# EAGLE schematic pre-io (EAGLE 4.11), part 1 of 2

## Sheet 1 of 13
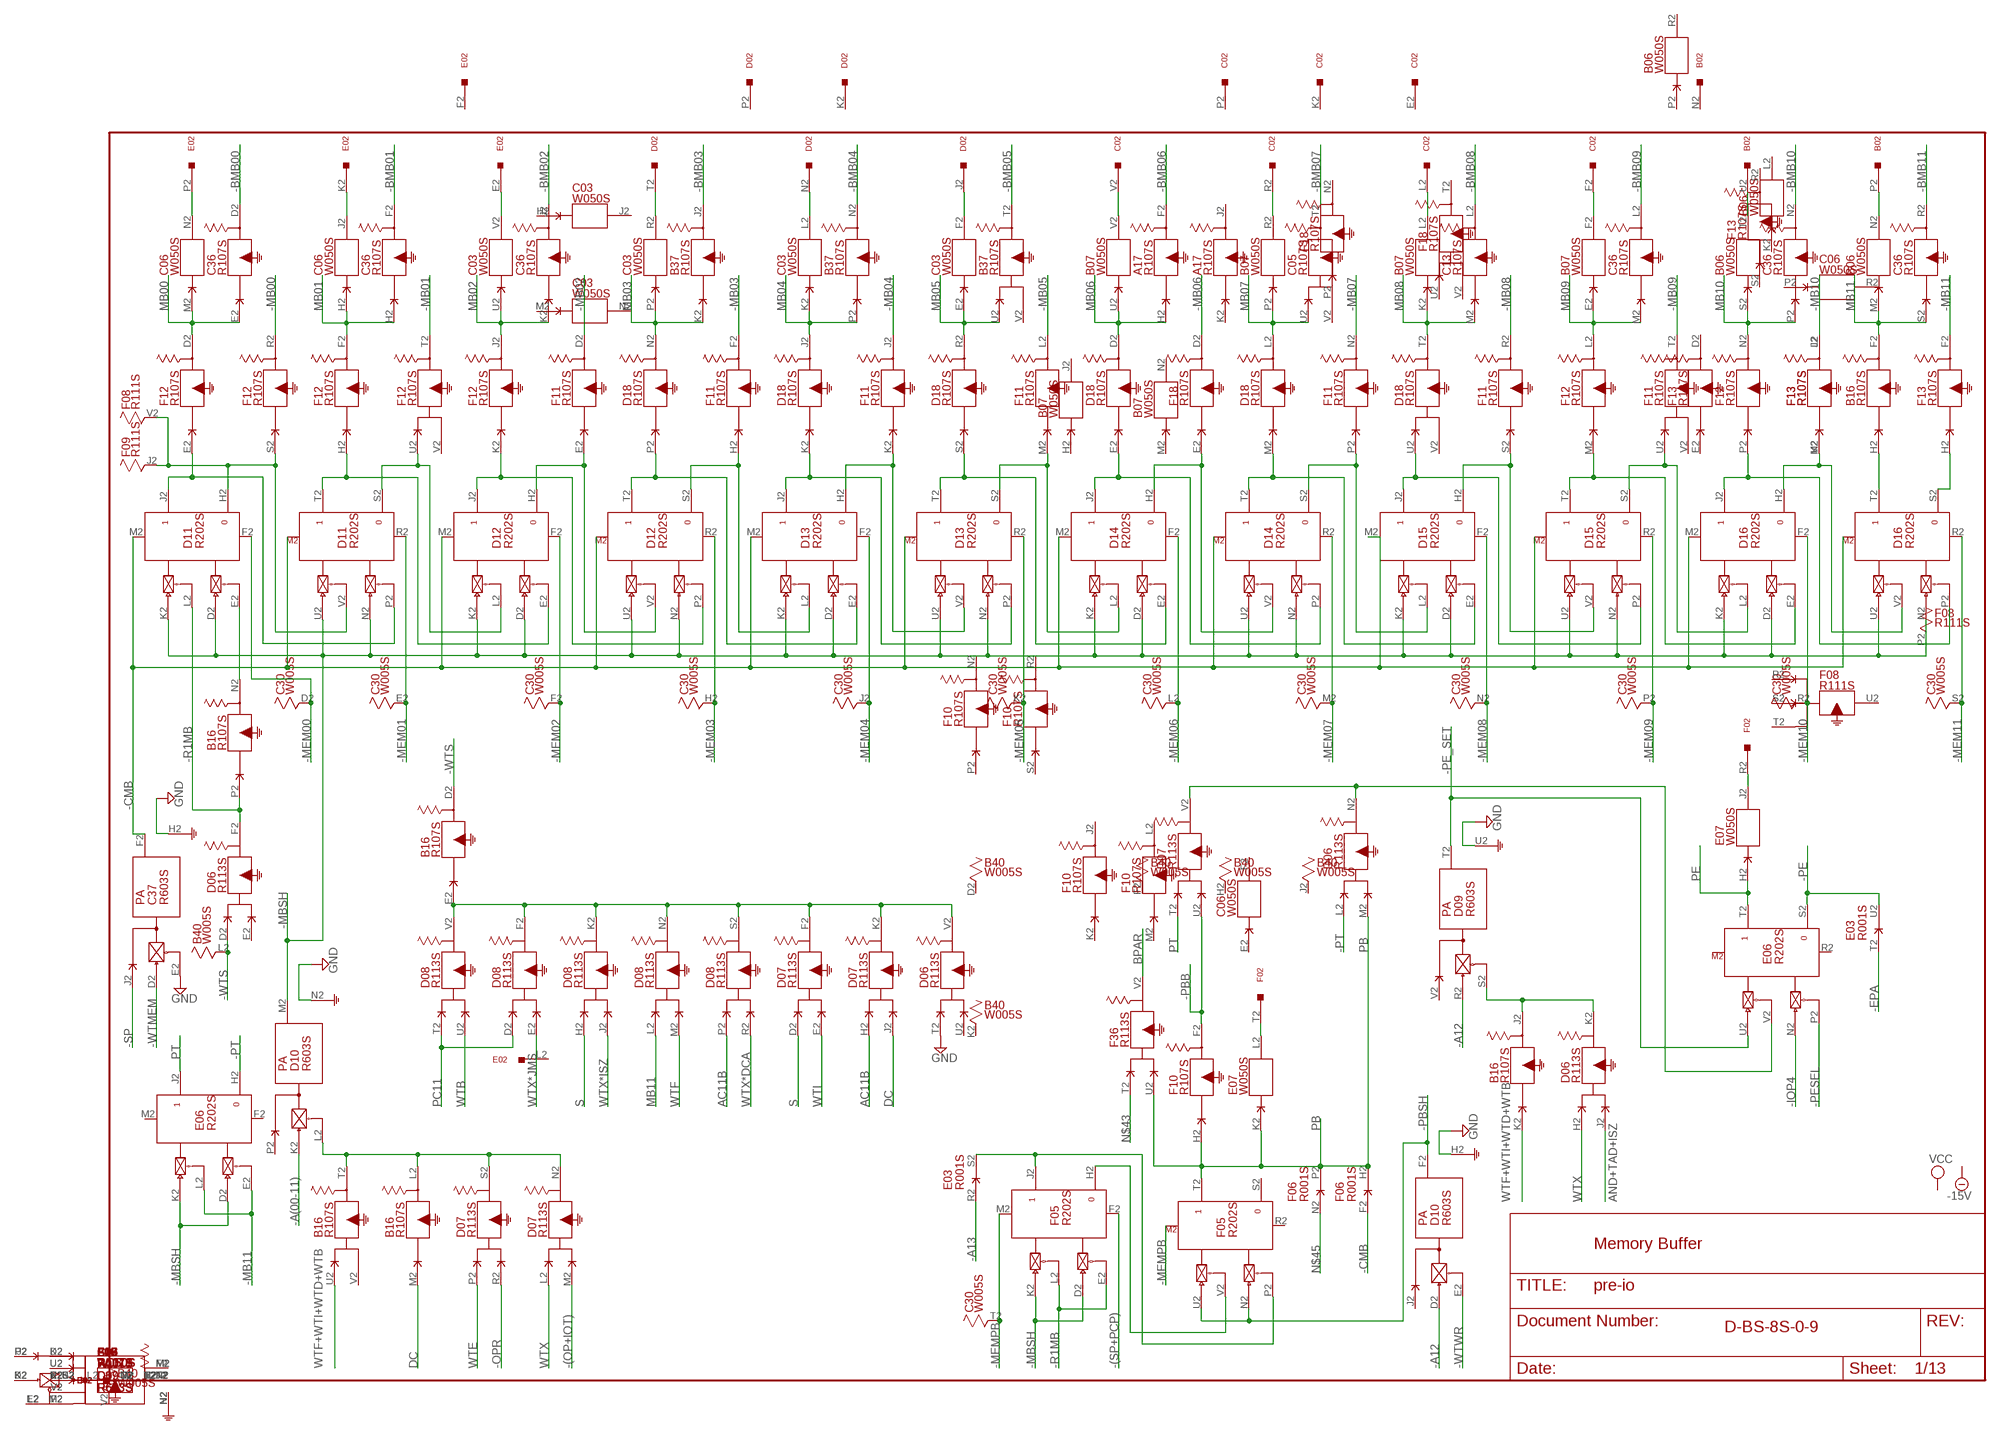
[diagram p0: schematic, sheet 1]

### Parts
A17  R107S  [H807S]
B02  W023S  [H807S]
B06  W050S  [H807S]
B07  W050S  [H807S]
B16  R107S  [H807S]
B37  R107S  [H807S]
B40  W005S  [H807S]
C02  W023S  [H807S]
C03  W050S  [H807S]
C05  R107S  [H807S]
C06  W050S  [H807S]
C13  R107S  [H807S]
C30  W005S  [H807S]
C36  R107S  [H807S]
C37  R603S  [H807S]
D02  W023S  [H807S]
D06  R113S  [H807S]
D07  R113S  [H807S]
D08  R113S  [H807S]
D09  R603S  [H807S]
D10  R603S  [H807S]
D11  R202S  [H807S]
D12  R202S  [H807S]
D13  R202S  [H807S]
D14  R202S  [H807S]
D15  R202S  [H807S]
D16  R202S  [H807S]
D18  R107S  [H807S]
E02  W023S  [H807S]
E03  R001S  [H807S]
E06  R202S  [H807S]
E07  W050S  [H807S]
F02  W023S  [H807S]
F05  R202S  [H807S]
F06  R001S  [H807S]
F08  R111S  [H807S]
F09  R111S  [H807S]
F10  R107S  [H807S]
F11  R107S  [H807S]
F12  R107S  [H807S]
F13  R107S  [H807S]
F18  R107S  [H807S]
F36  R113S  [H807S]

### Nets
-(OP+IOT): D07.M2(N:I$2) ; also sheet 6,9
-(SP+PCP): F05.F2(J:RESET) ; also sheet 3,7,8
-A12: D09.R2(T:PU0) D10.D2(F:PU0) ; also sheet 3,4,6,8
-A13: E03.R2(S:D) ; also sheet 4,5,6,7
-A(00-11): D10.K2(M:PU0) ; also sheet 3,4,5,7,9
-BMB00: C36.D2(D:O$1)
-BMB01: C36.F2(F:O$1)
-BMB02: C36.J2(J:O$1)
-BMB03: B37.J2(J:O$1)
-BMB04: B37.N2(N:O$1)
-BMB05: B37.T2(T:O$1)
-BMB06: A17.F2(F:O$1)
-BMB07: C05.T2(T:O$1)
-BMB08: C13.L2(L:O$1)
-BMB09: C36.L2(L:O$1)
-BMB10: C36.N2(N:O$1)
-BMB11: C36.R2(R:O$1)
-CMB: C37.F2(F:O) D11.M2(J:SET) D12.M2(J:SET) D13.M2(J:SET) D14.M2(J:SET) D15.M2(J:SET) D16.M2(J:SET) F06.F2(H:D)
-EPA: E03.T2(U:D) ; also sheet 8
-IOP4: E06.N2(T:PU0)
-MB00: F12.R2(R:O$1) ; also sheet 2
-MB01: F12.T2(T:O$1) ; also sheet 2
-MB02: F11.D2(D:O$1) ; also sheet 2
-MB03: F11.F2(F:O$1) ; also sheet 2
-MB04: F11.J2(J:O$1) ; also sheet 2,5
-MB05: F11.L2(L:O$1) ; also sheet 2,6
-MB06: F18.D2(D:O$1) ; also sheet 2,6,7
-MB07: F11.N2(N:O$1) ; also sheet 2,6
-MB08: F11.R2(R:O$1) ; also sheet 2,3
-MB09: F11.T2(T:O$1) ; also sheet 2
-MB10: F13.L2(L:O$1) ; also sheet 2,9
-MB11: E06.E2(J:EN0) E06.L2(J:EN1) F13.F2(F:O$1) ; also sheet 2,9
-MBSH: D10.M2(M:O) D11.D2(J:PU0) D11.K2(J:PU1) D11.N2(T:PU0) D11.U2(T:PU1) D12.D2(J:PU0) D12.K2(J:PU1) D12.N2(T:PU0) D12.U2(T:PU1) D13.D2(J:PU0) D13.K2(J:PU1) D13.N2(T:PU0) D13.U2(T:PU1) D14.D2(J:PU0) D14.K2(J:PU1) D14.N2(T:PU0) D14.U2(T:PU1) D15.D2(J:PU0) D15.K2(J:PU1) D15.N2(T:PU0) D15.U2(T:PU1) D16.D2(J:PU0) D16.K2(J:PU1) D16.N2(T:PU0) D16.U2(T:PU1) E06.D2(J:PU0) E06.K2(J:PU1) F05.D2(J:PU0) F05.K2(J:PU1)
-MEM00: C30.D2 D11.F2(J:RESET) ; also sheet 2
-MEM01: C30.E2 D11.R2(T:RESET) ; also sheet 2
-MEM02: C30.F2 D12.F2(J:RESET) ; also sheet 2
-MEM03: C30.H2 D12.R2(T:RESET) ; also sheet 2
-MEM04: C30.J2 D13.F2(J:RESET) ; also sheet 2
-MEM05: C30.K2 D13.R2(T:RESET) ; also sheet 2
-MEM06: C30.L2 D14.F2(J:RESET) ; also sheet 2
-MEM07: C30.M2 D14.R2(T:RESET) ; also sheet 2
-MEM08: C30.N2 D15.F2(J:RESET) ; also sheet 2
-MEM09: C30.P2 D15.R2(T:RESET) ; also sheet 2
-MEM10: C30.R2 D16.F2(J:RESET) ; also sheet 2
-MEM11: C30.S2 D16.R2(T:RESET) ; also sheet 2
-MEMPB: C30.T2 F05.M2(J:SET) ; also sheet 2
-OPR: D07.R2(S:I$2) ; also sheet 9
-PBB: D07.U2(V:I$2) F10.F2(F:O$1) ; also sheet 2
-PBSH: D10.F2(F:O) F05.N2(T:PU0) F05.U2(T:PU1)
-PE: E03.U2(U:E) E06.S2
-PE_SET: D09.T2(T:O) E06.U2(T:PU1)
-PESEL: E06.P2(T:EN0)
-PT: D06.L2(N:I$1) E06.H2
-R1MB: B16.P2(N:I$1) D06.F2(F:O$1) D11.L2(J:EN1) F05.E2(J:EN0) F05.L2(J:EN1)
-SP: C37.J2(F:I$1) ; also sheet 6,8
-WTMEM: C37.D2(F:PU0)
-WTS: B16.D2(D:O$1) B40.L2 D06.D2(F:I$1) ; also sheet 4,6
-WTWR: D10.E2(F:EN0) ; also sheet 6
AC11B: D07.H2(K:I$1) D08.P2(S:I$1) ; also sheet 7
AND+TAD+ISZ: D06.J2(K:I$2) ; also sheet 9
BPAR: F36.V2(V:O$1)
DC: B16.M2(L:I$1) D07.J2(K:I$2) ; also sheet 8
GND [Supply]: C37.E2(F:EN0) C37.H2(F:G) D06.T2(V:I$1) D09.U2(T:G) D10.H2(F:G) D10.N2(M:G) ; also sheet 2,3,4,5,6,7,8,9
MB00: C06.M2(N:I$1) C36.E2(D:I$1) F12.D2(D:O$1)
MB01: C06.H2(J:I$1) C36.H2(F:I$1) F12.F2(F:O$1)
MB02: C03.U2(V:I$1) C36.K2(J:I$1) F12.J2(J:O$1)
MB03: B37.K2(J:I$1) C03.P2(R:I$1) D18.N2(N:O$1)
MB04: B37.P2(N:I$1) C03.K2(L:I$1) D18.J2(J:O$1)
MB05: B37.U2(T:I$1) C03.E2(F:I$1) D18.R2(R:O$1) ; also sheet 3,9
MB06: A17.H2(F:I$1) B07.U2(V:I$1) D18.D2(D:O$1) ; also sheet 3,7,9
MB07: B07.P2(R:I$1) C05.U2(T:I$1) D18.L2(L:O$1) ; also sheet 3,9
MB08: B07.K2(L:I$1) C13.M2(L:I$1) D18.T2(T:O$1) ; also sheet 3,6,9
MB09: B07.E2(F:I$1) C36.M2(L:I$1) F12.L2(L:O$1) ; also sheet 3,9
MB10: B06.S2(T:I$1) C36.P2(N:I$1) F12.N2(N:O$1) ; also sheet 8,9
MB11: B06.M2(N:I$1) B16.F2(F:O$1) C36.S2(R:I$1) D08.L2(N:I$1) ; also sheet 6,7,9
N$1: D11.J2 D11.P2(T:EN0) F12.E2(D:I$1)
N$2: C06.N2(N:O$1) E02.P2
N$3: D11.H2 D11.V2(T:EN1) F08.V2 F09.J2 F12.S2(R:I$1)
N$4: D11.T2 D12.E2(J:EN0) F12.H2(F:I$1)
N$5: B16.E2(D:I$1) D06.V2(V:O$1) D07.F2(F:O$1) D07.K2(K:O$1) D08.F2(F:O$1) D08.K2(K:O$1) D08.N2(N:O$1) D08.S2(S:O$1) D08.V2(V:O$1)
N$6: D12.J2 D12.P2(T:EN0) F12.K2(J:I$1)
N$7: D12.T2 D13.E2(J:EN0) D18.P2(N:I$1)
N$8: D13.J2 D13.P2(T:EN0) D18.K2(J:I$1)
N$9: D13.T2 D14.E2(J:EN0) D18.S2(R:I$1)
N$10: D14.J2 D14.P2(T:EN0) D18.E2(D:I$1)
N$11: D14.T2 D15.E2(J:EN0) D18.M2(L:I$1)
N$12: D15.J2 D15.P2(T:EN0) D18.U2(T:I$1)
N$13: D15.H2 D15.V2(T:EN1) F11.S2(R:I$1)
N$14: D14.S2 D15.L2(J:EN1) F11.P2(N:I$1)
N$15: D14.H2 D14.V2(T:EN1) F18.E2(D:I$1)
N$16: D13.S2 D14.L2(J:EN1) F11.M2(L:I$1)
N$17: D15.T2 D16.E2(J:EN0) F12.M2(L:I$1)
N$18: D15.S2 D16.L2(J:EN1) F11.U2(T:I$1)
N$19: D16.J2 D16.P2(T:EN0) F12.P2(N:I$1)
N$20: D13.H2 D13.V2(T:EN1) F11.K2(J:I$1)
N$21: D12.S2 D13.L2(J:EN1) F11.H2(F:I$1)
N$22: D12.H2 D12.V2(T:EN1) F11.E2(D:I$1)
N$23: D11.S2 D12.L2(J:EN1) F12.U2(T:I$1)
N$24: D16.H2 D16.V2(T:EN1) F13.M2(L:I$1)
N$25: B16.H2(F:I$1) D16.T2
N$26: D16.S2 F13.H2(F:I$1)
N$27: C06.J2(J:O$1) E02.K2
N$28: C03.V2(V:O$1) E02.E2
N$29: C03.R2(R:O$1) D02.T2
N$30: C03.L2(L:O$1) D02.N2
N$31: C03.F2(F:O$1) D02.J2
N$32: B07.V2(V:O$1) C02.V2
N$33: B07.R2(R:O$1) C02.R2
N$34: B07.L2(L:O$1) C02.L2
N$35: B07.F2(F:O$1) C02.F2
N$36: B02.U2 B06.T2(T:O$1)
N$37: B02.P2 B06.N2(N:O$1)
N$38: B16.L2(L:O$1) B16.T2(T:O$1) D07.N2(N:O$1) D07.S2(S:O$1) D10.L2(M:EN0)
N$39: B16.N2(N:O$1) D11.E2(J:EN0)
N$40: B16.J2(J:O$1) D06.K2(K:O$1) D09.S2(T:EN0)
N$41: E07.J2(J:O$1) F02.R2
N$42: D06.N2(N:O$1) D07.V2(V:O$1) E06.V2(T:EN1)
N$43: F36.T2(V:I$1)
N$44: E07.L2(L:O$1) F02.T2
N$45: F06.N2(P:D)
N$46: F05.H2 F05.V2(T:EN1)
N$47: E03.S2(S:E) F05.J2 F05.P2(T:EN0)
PB: D06.M2(N:I$2) E07.K2(L:I$1) F05.T2 F06.H2(H:E) F06.P2(P:E) F10.H2(F:I$1) F36.U2(V:I$2)
PC11: D08.D2(F:I$1) D08.T2(V:I$1) ; also sheet 5,7
PE: E06.T2 E07.H2(J:I$1)
PT: D07.T2(V:I$1) E06.J2
S: D07.D2(F:I$1) D08.H2(K:I$1) ; also sheet 5,7
WTB: D08.U2(V:I$2) ; also sheet 6
WTE: D07.P2(S:I$1) ; also sheet 3,6,8
WTF: D08.M2(N:I$2) ; also sheet 3,5,6,8
WTF+WTI+WTD+WTB: B16.K2(J:I$1) B16.U2(T:I$1) ; also sheet 6
WTI: D07.E2(F:I$2) ; also sheet 6
WTX: D06.H2(K:I$1) D07.L2(N:I$1) ; also sheet 3,6,7
WTX*DCA: D08.R2(S:I$2) ; also sheet 6
WTX*ISZ: D08.J2(K:I$2) ; also sheet 6
WTX*JMS: D08.E2(F:I$2) ; also sheet 6
Unconnected: A17.D2(D:O$1) A17.E2(D:I$1) A17.L2(L:O$1) A17.M2(L:I$1) A17.R2(R:O$1) A17.S2(R:I$1) A17.T2(T:O$1) A17.U2(T:I$1) A17.V2(T:I$2) B02.A2 B02.B2 B02.C2 B02.E2 B02.F2 B02.H2 B02.J2 B02.K2 B02.L2 B02.M2 B02.R2 B02.S2 B02.V2 B06.E2(F:I$1) B06.F2(F:O$1) B06.H2(J:I$1) B06.J2(J:O$1) B16.R2(R:O$1) B16.S2(R:I$1) B16.V2(T:I$2) B37.D2(D:O$1) B37.E2(D:I$1) B37.F2(F:O$1) B37.H2(F:I$1) B37.L2(L:O$1) B37.M2(L:I$1) B37.R2(R:O$1) B37.S2(R:I$1) B37.V2(T:I$2) B40.E2 B40.M2 B40.N2 B40.P2 B40.R2 B40.S2 B40.T2 B40.U2 C02.A2 C02.B2 C02.C2 C02.D2 C02.H2 C02.J2 C02.M2 C02.N2 C02.S2 C02.T2 C05.D2(D:O$1) C05.E2(D:I$1) C05.F2(F:O$1) C05.H2(F:I$1) C05.J2(J:O$1) C05.K2(J:I$1) C05.L2(L:O$1) C05.M2(L:I$1) C05.N2(N:O$1) C05.P2(N:I$1) C05.R2(R:O$1) C05.S2(R:I$1) C05.V2(T:I$2) C06.S2(T:I$1) C06.T2(T:O$1) C06.U2(V:I$1) C06.V2(V:O$1) C30.U2 C30.V2 C36.T2(T:O$1) C36.U2(T:I$1) C36.V2(T:I$2) D02.A2 D02.B2 D02.C2 D02.D2 D02.E2 D02.F2 D02.H2 D02.L2 D02.M2 D02.R2 D02.S2 D02.V2 D06.E2(F:I$2) D06.P2(S:I$1) D06.R2(S:I$2) D06.S2(S:O$1) D06.U2(V:I$2) D18.F2(F:O$1) D18.H2(F:I$1) D18.V2(T:I$2) E02.A2 E02.B2 E02.C2 E02.D2 E02.H2 E02.J2 E02.M2 E02.N2 E02.S2 E02.T2 E02.U2 E02.V2 E03.D2(E:D) E03.E2(E:E) E03.F2(H:D) E03.H2(H:E) E03.J2(K:D) E03.K2(K:E) E03.L2(M:D) E03.M2(M:E) E03.N2(P:D) E03.P2(P:E) E06.F2(J:RESET) E06.M2(J:SET) E06.R2(T:RESET) E07.E2(F:I$1) E07.F2(F:O$1) E07.M2(N:I$1) E07.N2(N:O$1) E07.P2(R:I$1) E07.R2(R:O$1) E07.S2(T:I$1) E07.T2(T:O$1) E07.U2(V:I$1) E07.V2(V:O$1) F02.A2 F02.B2 F02.C2 F02.D2 F02.E2 F02.F2 F02.H2 F02.J2 F02.K2 F02.L2 F02.M2 F02.N2 F02.P2 F02.S2 F02.U2 F02.V2 F05.R2(T:RESET) F05.S2 F06.D2(E:D) F06.E2(E:E) F06.J2(K:D) F06.K2(K:E) F06.R2(S:D) F06.S2(S:E) F06.T2(U:D) F06.U2(U:E) F08.D2(H:I$1) F08.E2(H:I$2) F08.F2(H:I$3) F08.H2(H:O$1) F08.J2 F09.K2(N:I$1) F09.L2(N:I$2) F09.M2(N:I$3) F09.N2(N:O$1) F09.P2 F09.R2(U:I$1) F09.S2(U:I$2) F09.T2(U:I$3) F09.U2(U:O$1) F09.V2 F10.D2(D:O$1) F10.E2(D:I$1) F11.V2(T:I$2) F12.V2(T:I$2) F18.R2(R:O$1) F18.S2(R:I$1) F36.D2(F:I$1) F36.E2(F:I$2) F36.F2(F:O$1) F36.H2(K:I$1) F36.J2(K:I$2) F36.K2(K:O$1) F36.L2(N:I$1) F36.M2(N:I$2) F36.N2(N:O$1) F36.P2(S:I$1) F36.R2(S:I$2) F36.S2(S:O$1)

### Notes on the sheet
- Memory Buffer
- D-BS-8S-0-9

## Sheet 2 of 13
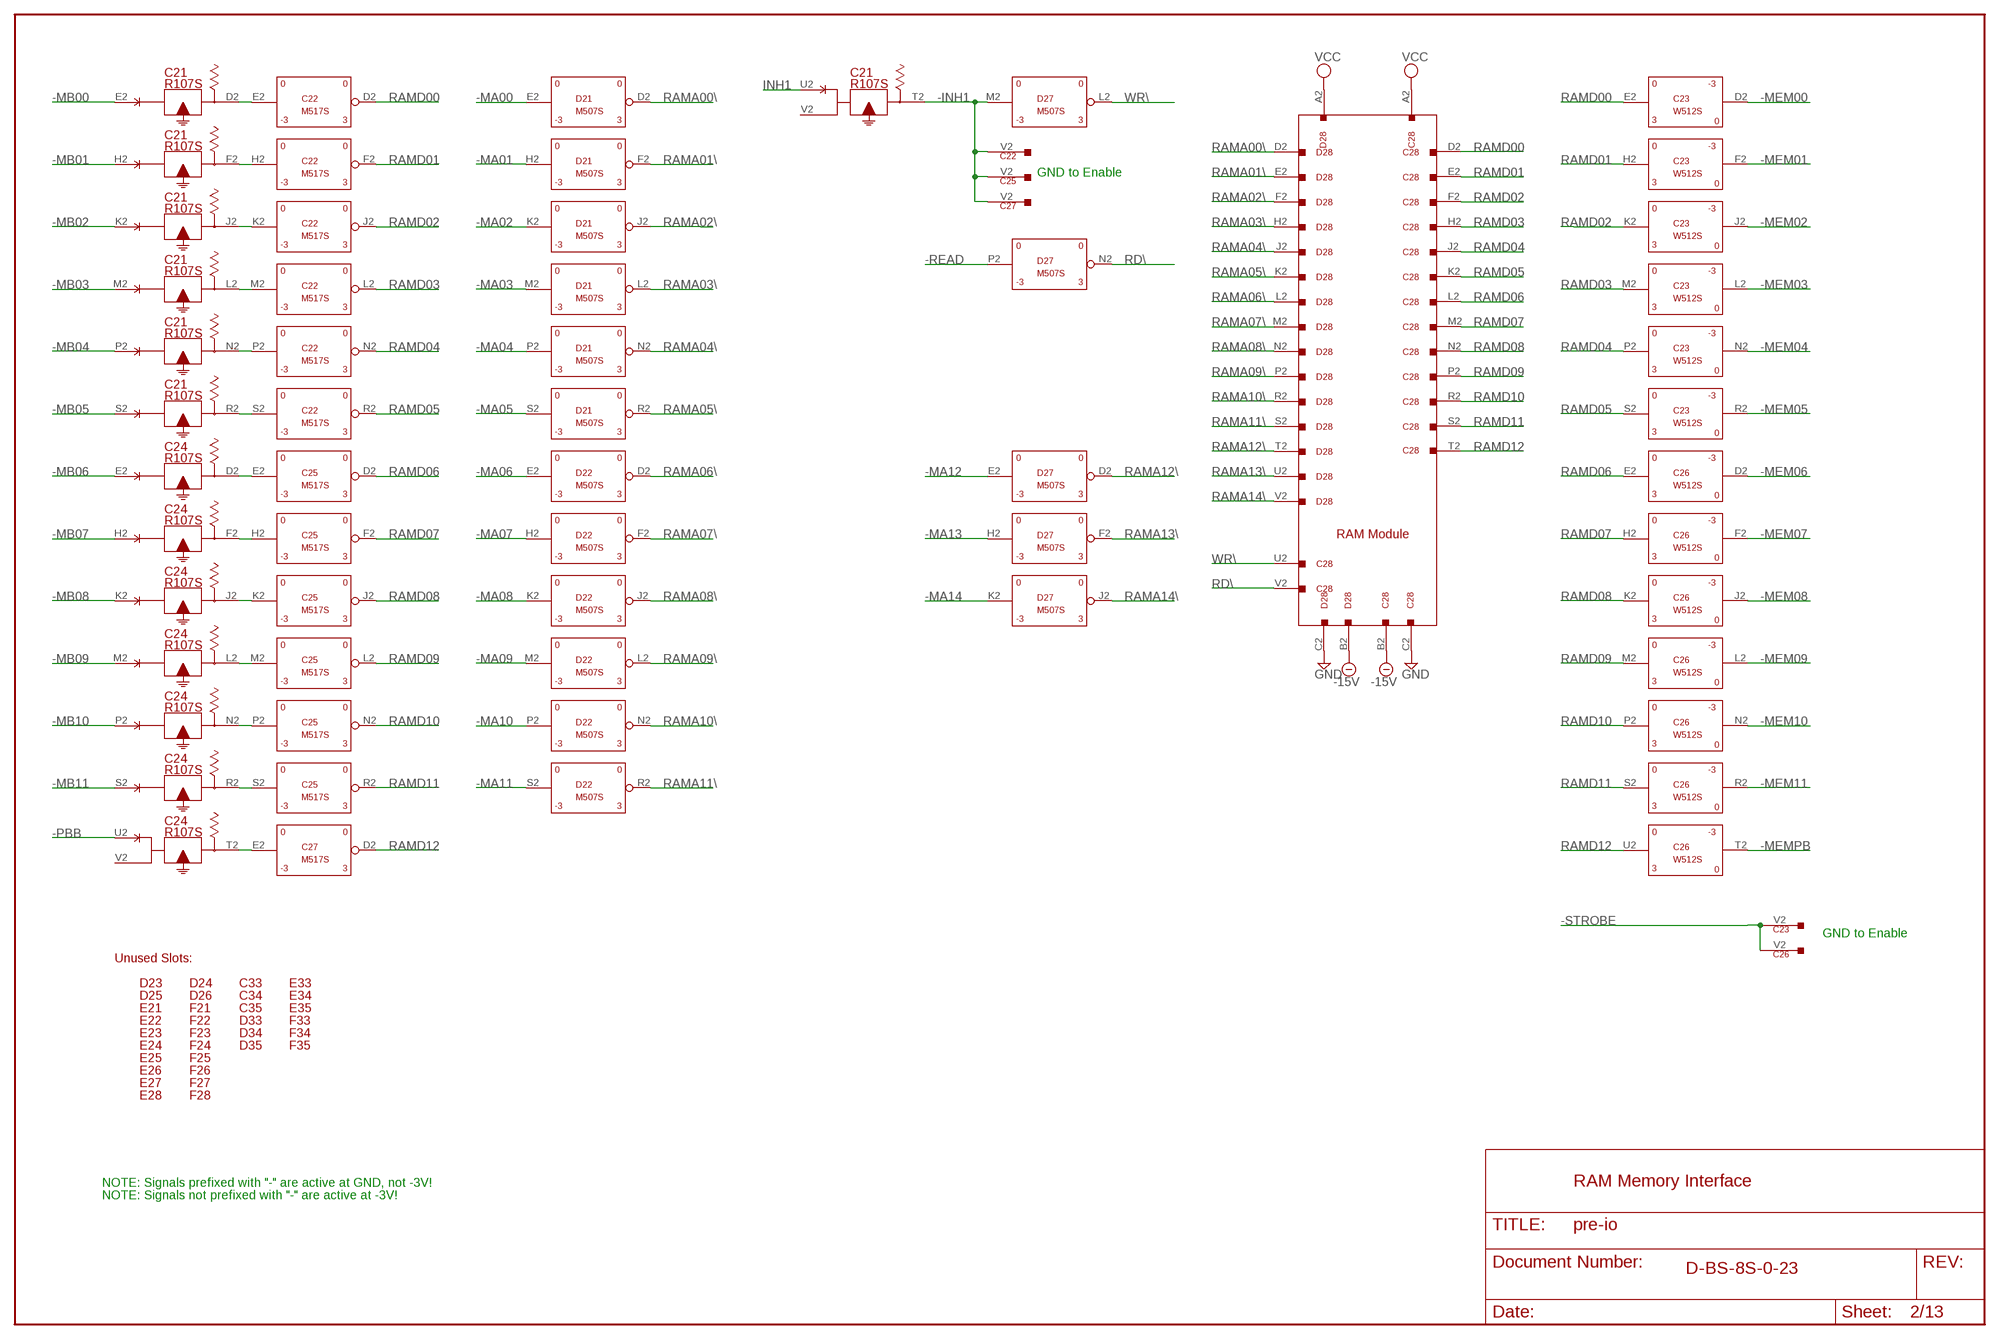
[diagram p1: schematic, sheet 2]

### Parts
C21  R107S  [H807S]
C22  M517S  [H807S]
C23  W512S  [H807S]
C24  R107S  [H807S]
C25  M517S  [H807S]
C26  W512S  [H807S]
C27  M517S  [H807S]
C28  W023S  [H807S]
C33  EMPTYS  [H807S]
C34  EMPTYS  [H807S]
C35  EMPTYS  [H807S]
D21  M507S  [H807S]
D22  M507S  [H807S]
D23  EMPTYS  [H807S]
D24  EMPTYS  [H807S]
D25  EMPTYS  [H807S]
D26  EMPTYS  [H807S]
D27  M507S  [H807S]
D28  W023S  [H807S]
D33  EMPTYS  [H807S]
D34  EMPTYS  [H807S]
D35  EMPTYS  [H807S]
E21  EMPTYS  [H807S]
E22  EMPTYS  [H807S]
E23  EMPTYS  [H807S]
E24  EMPTYS  [H807S]
E25  EMPTYS  [H807S]
E26  EMPTYS  [H807S]
E27  EMPTYS  [H807S]
E28  EMPTYS  [H807S]
E33  EMPTYS  [H807S]
E34  EMPTYS  [H807S]
E35  EMPTYS  [H807S]
F21  EMPTYS  [H807S]
F22  EMPTYS  [H807S]
F23  EMPTYS  [H807S]
F24  EMPTYS  [H807S]
F25  EMPTYS  [H807S]
F26  EMPTYS  [H807S]
F27  EMPTYS  [H807S]
F28  EMPTYS  [H807S]
F33  EMPTYS  [H807S]
F34  EMPTYS  [H807S]
F35  EMPTYS  [H807S]

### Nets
-15V [Supply]: C28.B2 D28.B2
-INH1: C21.T2(T:O$1) C22.V2 C25.V2 C27.V2 D27.M2(L:IN)
-MA00: D21.E2(D:IN)
-MA01: D21.H2(F:IN)
-MA02: D21.K2(J:IN)
-MA03: D21.M2(L:IN)
-MA04: D21.P2(N:IN) ; also sheet 6
-MA05: D21.S2(R:IN)
-MA06: D22.E2(D:IN)
-MA07: D22.H2(F:IN)
-MA08: D22.K2(J:IN)
-MA09: D22.M2(L:IN)
-MA10: D22.P2(N:IN)
-MA11: D22.S2(R:IN) ; also sheet 5
-MA12: D27.E2(D:IN)
-MA13: D27.H2(F:IN)
-MA14: D27.K2(J:IN)
-MB00: C21.E2(D:I$1) ; also sheet 1
-MB01: C21.H2(F:I$1) ; also sheet 1
-MB02: C21.K2(J:I$1) ; also sheet 1
-MB03: C21.M2(L:I$1) ; also sheet 1
-MB04: C21.P2(N:I$1) ; also sheet 1,5
-MB05: C21.S2(R:I$1) ; also sheet 1,6
-MB06: C24.E2(D:I$1) ; also sheet 1,6,7
-MB07: C24.H2(F:I$1) ; also sheet 1,6
-MB08: C24.K2(J:I$1) ; also sheet 1,3
-MB09: C24.M2(L:I$1) ; also sheet 1
-MB10: C24.P2(N:I$1) ; also sheet 1,9
-MB11: C24.S2(R:I$1) ; also sheet 1,9
-MEM00: C23.D2(OUT) ; also sheet 1
-MEM01: C23.F2(OUT) ; also sheet 1
-MEM02: C23.J2(OUT) ; also sheet 1
-MEM03: C23.L2(OUT) ; also sheet 1
-MEM04: C23.N2(OUT) ; also sheet 1
-MEM05: C23.R2(OUT) ; also sheet 1
-MEM06: C26.D2(OUT) ; also sheet 1
-MEM07: C26.F2(OUT) ; also sheet 1
-MEM08: C26.J2(OUT) ; also sheet 1
-MEM09: C26.L2(OUT) ; also sheet 1
-MEM10: C26.N2(OUT) ; also sheet 1
-MEM11: C26.R2(OUT) ; also sheet 1
-MEMPB: C26.T2(OUT) ; also sheet 1
-PBB: C24.U2(T:I$1) ; also sheet 1
-READ: D27.P2(N:IN)
-STROBE: C23.V2 C26.V2
GND [Supply]: C28.C2 D28.C2 ; also sheet 1,3,4,5,6,7,8,9
INH1: C21.U2(T:I$1)
N$49: C24.D2(D:O$1) C25.E2(D:IN)
N$50: C21.R2(R:O$1) C22.S2(R:IN)
N$51: C21.N2(N:O$1) C22.P2(N:IN)
N$52: C21.L2(L:O$1) C22.M2(L:IN)
N$55: C21.J2(J:O$1) C22.K2(J:IN)
N$56: C21.F2(F:O$1) C22.H2(F:IN)
N$57: C21.D2(D:O$1) C22.E2(D:IN)
N$58: C24.F2(F:O$1) C25.H2(F:IN)
N$59: C24.J2(J:O$1) C25.K2(J:IN)
N$60: C24.L2(L:O$1) C25.M2(L:IN)
N$61: C24.N2(N:O$1) C25.P2(N:IN)
N$62: C24.R2(R:O$1) C25.S2(R:IN)
N$63: C24.T2(T:O$1) C27.E2(D:IN)
RAMA00\: D21.D2(D:OUT) D28.D2
RAMA01\: D21.F2(F:OUT) D28.E2
RAMA02\: D21.J2(J:OUT) D28.F2
RAMA03\: D21.L2(L:OUT) D28.H2
RAMA04\: D21.N2(N:OUT) D28.J2
RAMA05\: D21.R2(R:OUT) D28.K2
RAMA06\: D22.D2(D:OUT) D28.L2
RAMA07\: D22.F2(F:OUT) D28.M2
RAMA08\: D22.J2(J:OUT) D28.N2
RAMA09\: D22.L2(L:OUT) D28.P2
RAMA10\: D22.N2(N:OUT) D28.R2
RAMA11\: D22.R2(R:OUT) D28.S2
RAMA12\: D27.D2(D:OUT) D28.T2
RAMA13\: D27.F2(F:OUT) D28.U2
RAMA14\: D27.J2(J:OUT) D28.V2
RAMD00: C22.D2(D:OUT) C23.E2(IN) C28.D2
RAMD01: C22.F2(F:OUT) C23.H2(IN) C28.E2
RAMD02: C22.J2(J:OUT) C23.K2(IN) C28.F2
RAMD03: C22.L2(L:OUT) C23.M2(IN) C28.H2
RAMD04: C22.N2(N:OUT) C23.P2(IN) C28.J2
RAMD05: C22.R2(R:OUT) C23.S2(IN) C28.K2
RAMD06: C25.D2(D:OUT) C26.E2(IN) C28.L2
RAMD07: C25.F2(F:OUT) C26.H2(IN) C28.M2
RAMD08: C25.J2(J:OUT) C26.K2(IN) C28.N2
RAMD09: C25.L2(L:OUT) C26.M2(IN) C28.P2
RAMD10: C25.N2(N:OUT) C26.P2(IN) C28.R2
RAMD11: C25.R2(R:OUT) C26.S2(IN) C28.S2
RAMD12: C26.U2(IN) C27.D2(D:OUT) C28.T2
RD\: C28.V2 D27.N2(N:OUT)
VCC [Supply]: C28.A2 D28.A2
WR\: C28.U2 D27.L2(L:OUT)
Unconnected: C21.V2(T:I$2) C23.T2(OUT) C23.U2(IN) C24.V2(T:I$2) C27.F2(F:OUT) C27.H2(F:IN) C27.J2(J:OUT) C27.K2(J:IN) C27.L2(L:OUT) C27.M2(L:IN) C27.N2(N:OUT) C27.P2(N:IN) C27.R2(R:OUT) C27.S2(R:IN) D27.R2(R:OUT) D27.S2(R:IN)

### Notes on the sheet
- GND to Enable
- RAM Module
- GND to Enable
- Unused Slots:
- NOTE: Signals prefixed with "-" are active at GND, not -3V! | RAM Memory Interface
- NOTE: Signals not prefixed with "-" are active at -3V!
- D-BS-8S-0-23

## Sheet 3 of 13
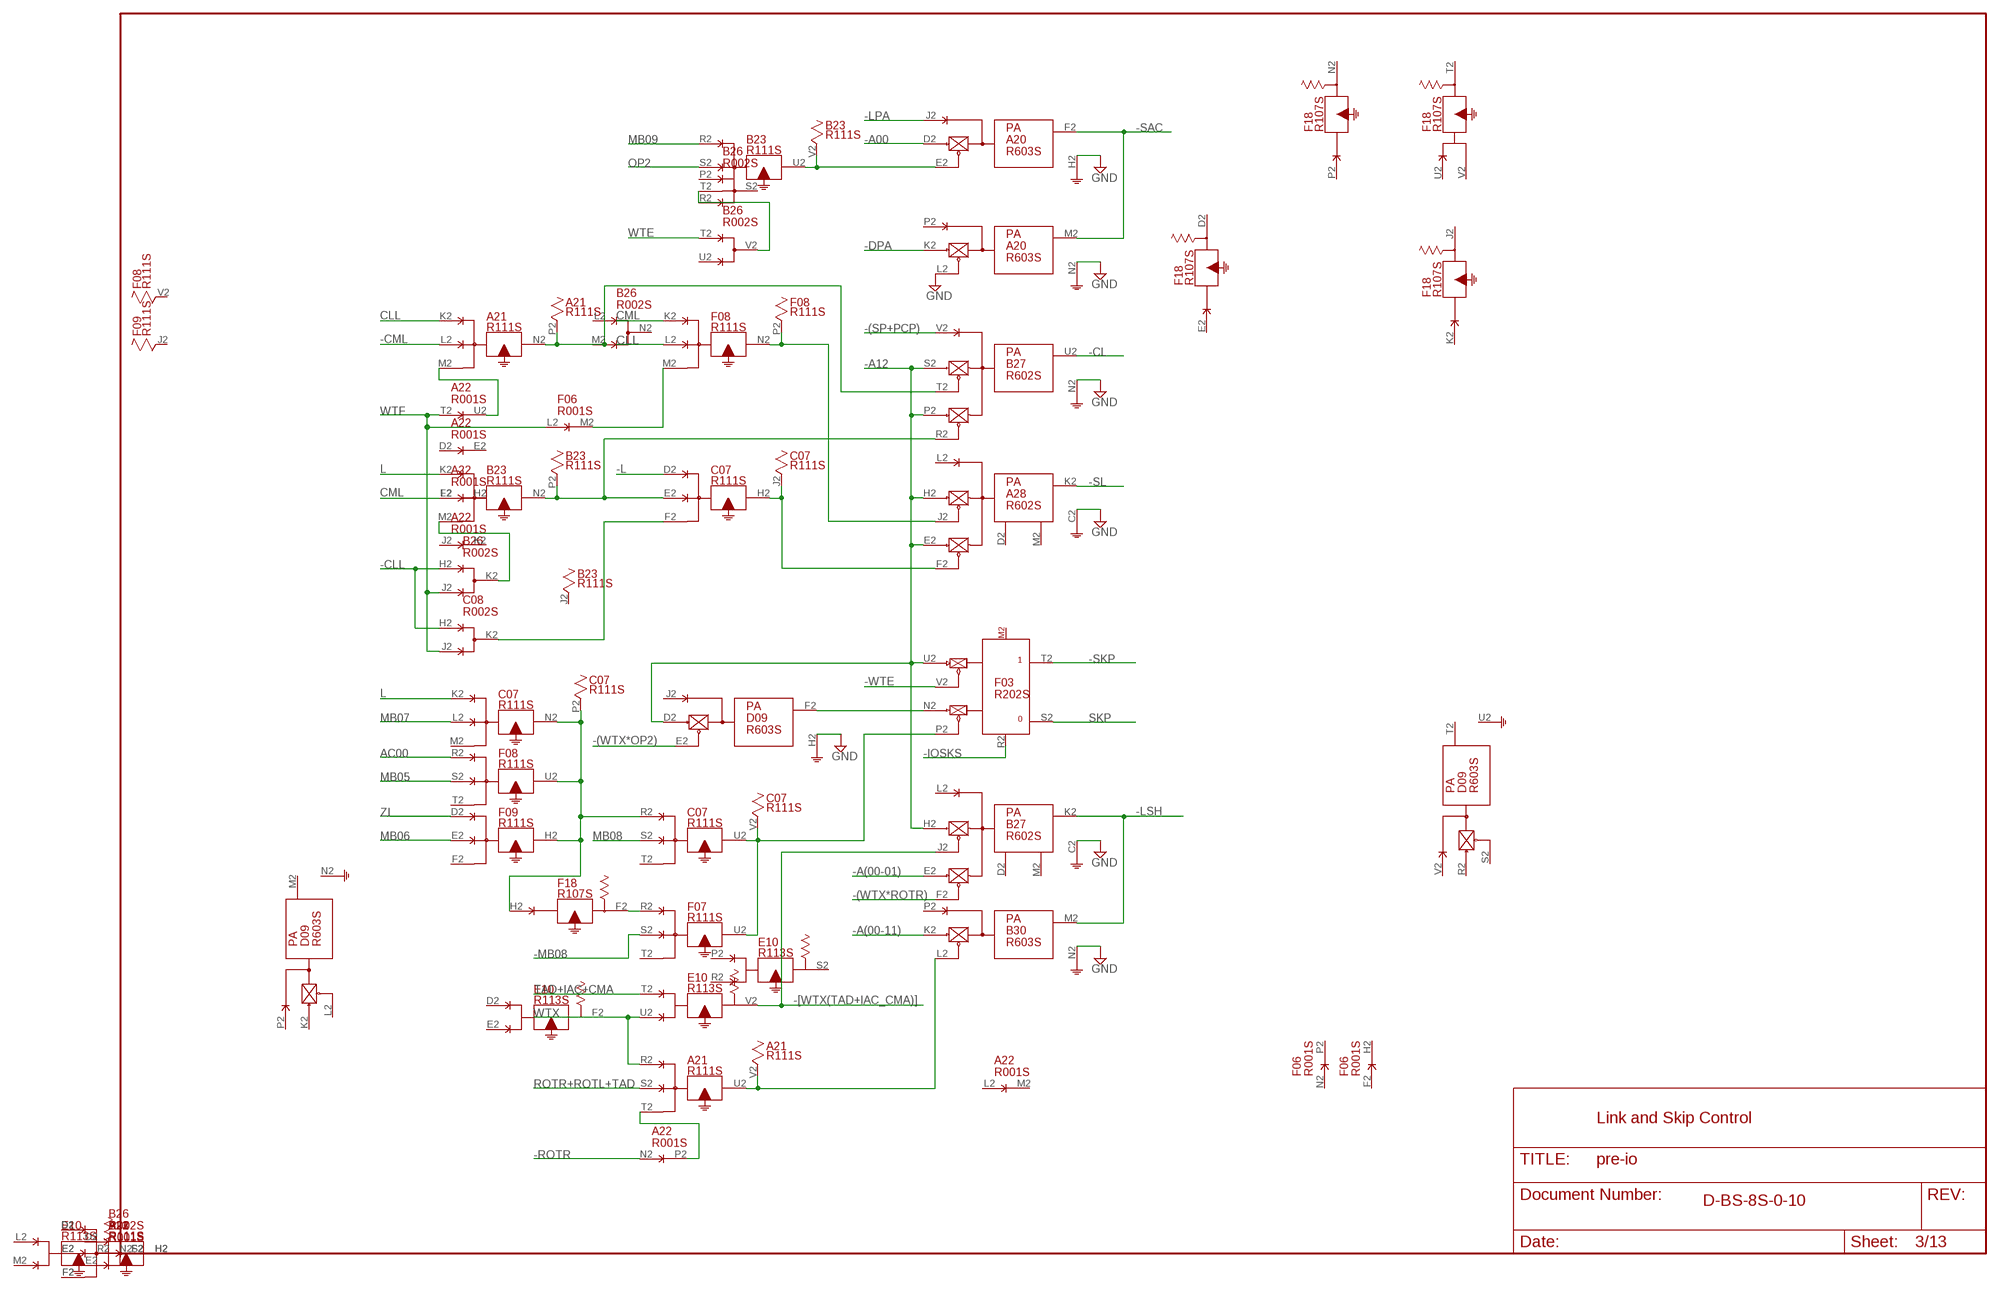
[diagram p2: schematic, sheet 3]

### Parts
A20  R603S  [H807S]
A21  R111S  [H807S]
A22  R001S  [H807S]
A28  R602S  [H807S]
B23  R111S  [H807S]
B26  R002S  [H807S]
B27  R602S  [H807S]
B30  R603S  [H807S]
C07  R111S  [H807S]
C08  R002S  [H807S]
E10  R113S  [H807S]
F03  R202S  [H807S]
F07  R111S  [H807S]

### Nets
-(SP+PCP): B27.V2(U:L) ; also sheet 1,7,8
-(WTX*OP2): D09.E2(F:EN0) ; also sheet 7
-(WTX*ROTR): B27.F2(K:F)
-[WTX(TAD+IAC_CMA)]: B27.J2(K:J) E10.V2(V:O$1)
-A00: A20.D2(F:PU0) ; also sheet 4,5,9
-A12: A28.E2(K:E) A28.H2(K:H) B27.H2(K:H) B27.P2(U:E) B27.S2(U:H) D09.D2(F:PU0) F03.U2(T:PU1) ; also sheet 1,4,6,8
-A(00-01): B27.E2(K:E) ; also sheet 4
-A(00-11): B30.K2(M:PU0) ; also sheet 1,4,5,7,9
-CL: B27.U2(U:K)
-CLL: B26.H2(K:D) C08.H2(K:D) ; also sheet 9
-CML: A21.L2(N:I$2) ; also sheet 9
-DPA: A20.K2(M:PU0) ; also sheet 8
-IOSKS: F03.R2(T:RESET)
-L: C07.D2(H:I$1)
-LPA: A20.J2(F:I$1) ; also sheet 8
-LSH: B27.K2(K:K) B30.M2(M:O)
-MB08: F07.S2(U:I$2) ; also sheet 1,2
-ROTR: A22.N2(P:D) ; also sheet 9
-SAC: A20.F2(F:O) A20.M2(M:O) ; also sheet 8
-SKP: F03.T2
-SL: A28.K2(K:K)
-WTE: F03.V2(T:EN1) ; also sheet 6
AC00: F08.R2(U:I$1)
CLL: A21.K2(N:I$1) F08.L2(N:I$2) ; also sheet 9
CML: B23.L2(N:I$2) F08.K2(N:I$1) ; also sheet 9
GND [Supply]: A20.H2(F:G) A20.L2(M:EN0) A20.N2(M:G) A28.C2(K:GND) B27.C2(K:GND) B27.N2(U:C) B30.N2(M:G) D09.H2(F:G) ; also sheet 1,2,4,5,6,7,8,9
L: B23.K2(N:I$1) C07.K2(N:I$1) ; also sheet 7
MB05: F08.S2(U:I$2) ; also sheet 1,9
MB06: F09.E2(H:I$2) ; also sheet 1,7,9
MB07: C07.L2(N:I$2) ; also sheet 1,9
MB08: C07.S2(U:I$2) ; also sheet 1,6,9
MB09: B23.R2(U:I$1) ; also sheet 1,9
N$48: A20.E2(F:EN0) B23.U2(U:O$1) B23.V2
N$53: B23.T2(U:I$3) B26.V2(V:F)
N$54: A28.J2(K:J) F08.N2(N:O$1) F08.P2
N$64: A21.N2(N:O$1) A21.P2 B27.T2(U:J)
N$65: B23.N2(N:O$1) B23.P2 B27.R2(U:F) C07.E2(H:I$2)
N$66: A28.F2(K:F) C07.H2(H:O$1) C07.J2
N$67: B23.M2(N:I$3) B26.K2(K:F)
N$68: F06.M2(M:E) F08.M2(N:I$3)
N$69: C07.F2(H:I$3) C08.K2(K:F)
N$71: D09.F2(F:O) F03.N2(T:PU0)
N$72: C07.U2(U:O$1) C07.V2 F03.P2(T:EN0) F07.U2(U:O$1)
N$73: F07.R2(U:I$1) F18.F2(F:O$1)
N$74: C07.N2(N:O$1) C07.P2 C07.R2(U:I$1) F08.U2(U:O$1) F09.H2(H:O$1) F18.H2(F:I$1)
N$75: A21.U2(U:O$1) A21.V2 B30.L2(M:EN0)
N$76: A21.T2(U:I$3) A22.P2(P:E)
N$79: A21.M2(N:I$3) A22.U2(U:E)
OP2: B23.S2(U:I$2) ; also sheet 6,7,8,9
ROTR+ROTL+TAD: A21.S2(U:I$2) ; also sheet 9
SKP: F03.S2 ; also sheet 9
TAD+IAC+CMA: E10.T2(V:I$1) ; also sheet 9
WTE: B26.T2(V:D) ; also sheet 1,6,8
WTF: A22.T2(U:D) B26.J2(K:E) C08.J2(K:E) F06.L2(M:D) ; also sheet 1,5,6,8
WTX: A21.R2(U:I$1) E10.U2(V:I$2) ; also sheet 1,6,7
ZI: F09.D2(H:I$1)
Unconnected: A21.J2 B27.D2(K:D) B27.L2(K:L) B27.M2(K:M) C07.M2(N:I$3) C07.T2(U:I$3) C08.L2(N:D) C08.M2(N:E) C08.N2(N:F) E10.H2(K:I$1) E10.J2(K:I$2) E10.K2(K:O$1) F03.D2(J:PU0) F03.E2(J:EN0) F03.F2(J:RESET) F03.H2 F03.J2 F03.K2(J:PU1) F03.L2(J:EN1) F03.M2(J:SET) F07.K2(N:I$1) F07.L2(N:I$2) F07.M2(N:I$3) F07.N2(N:O$1) F07.P2 F07.V2 F08.T2(U:I$3) F09.F2(H:I$3)

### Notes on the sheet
- Link and Skip Control
- D-BS-8S-0-10

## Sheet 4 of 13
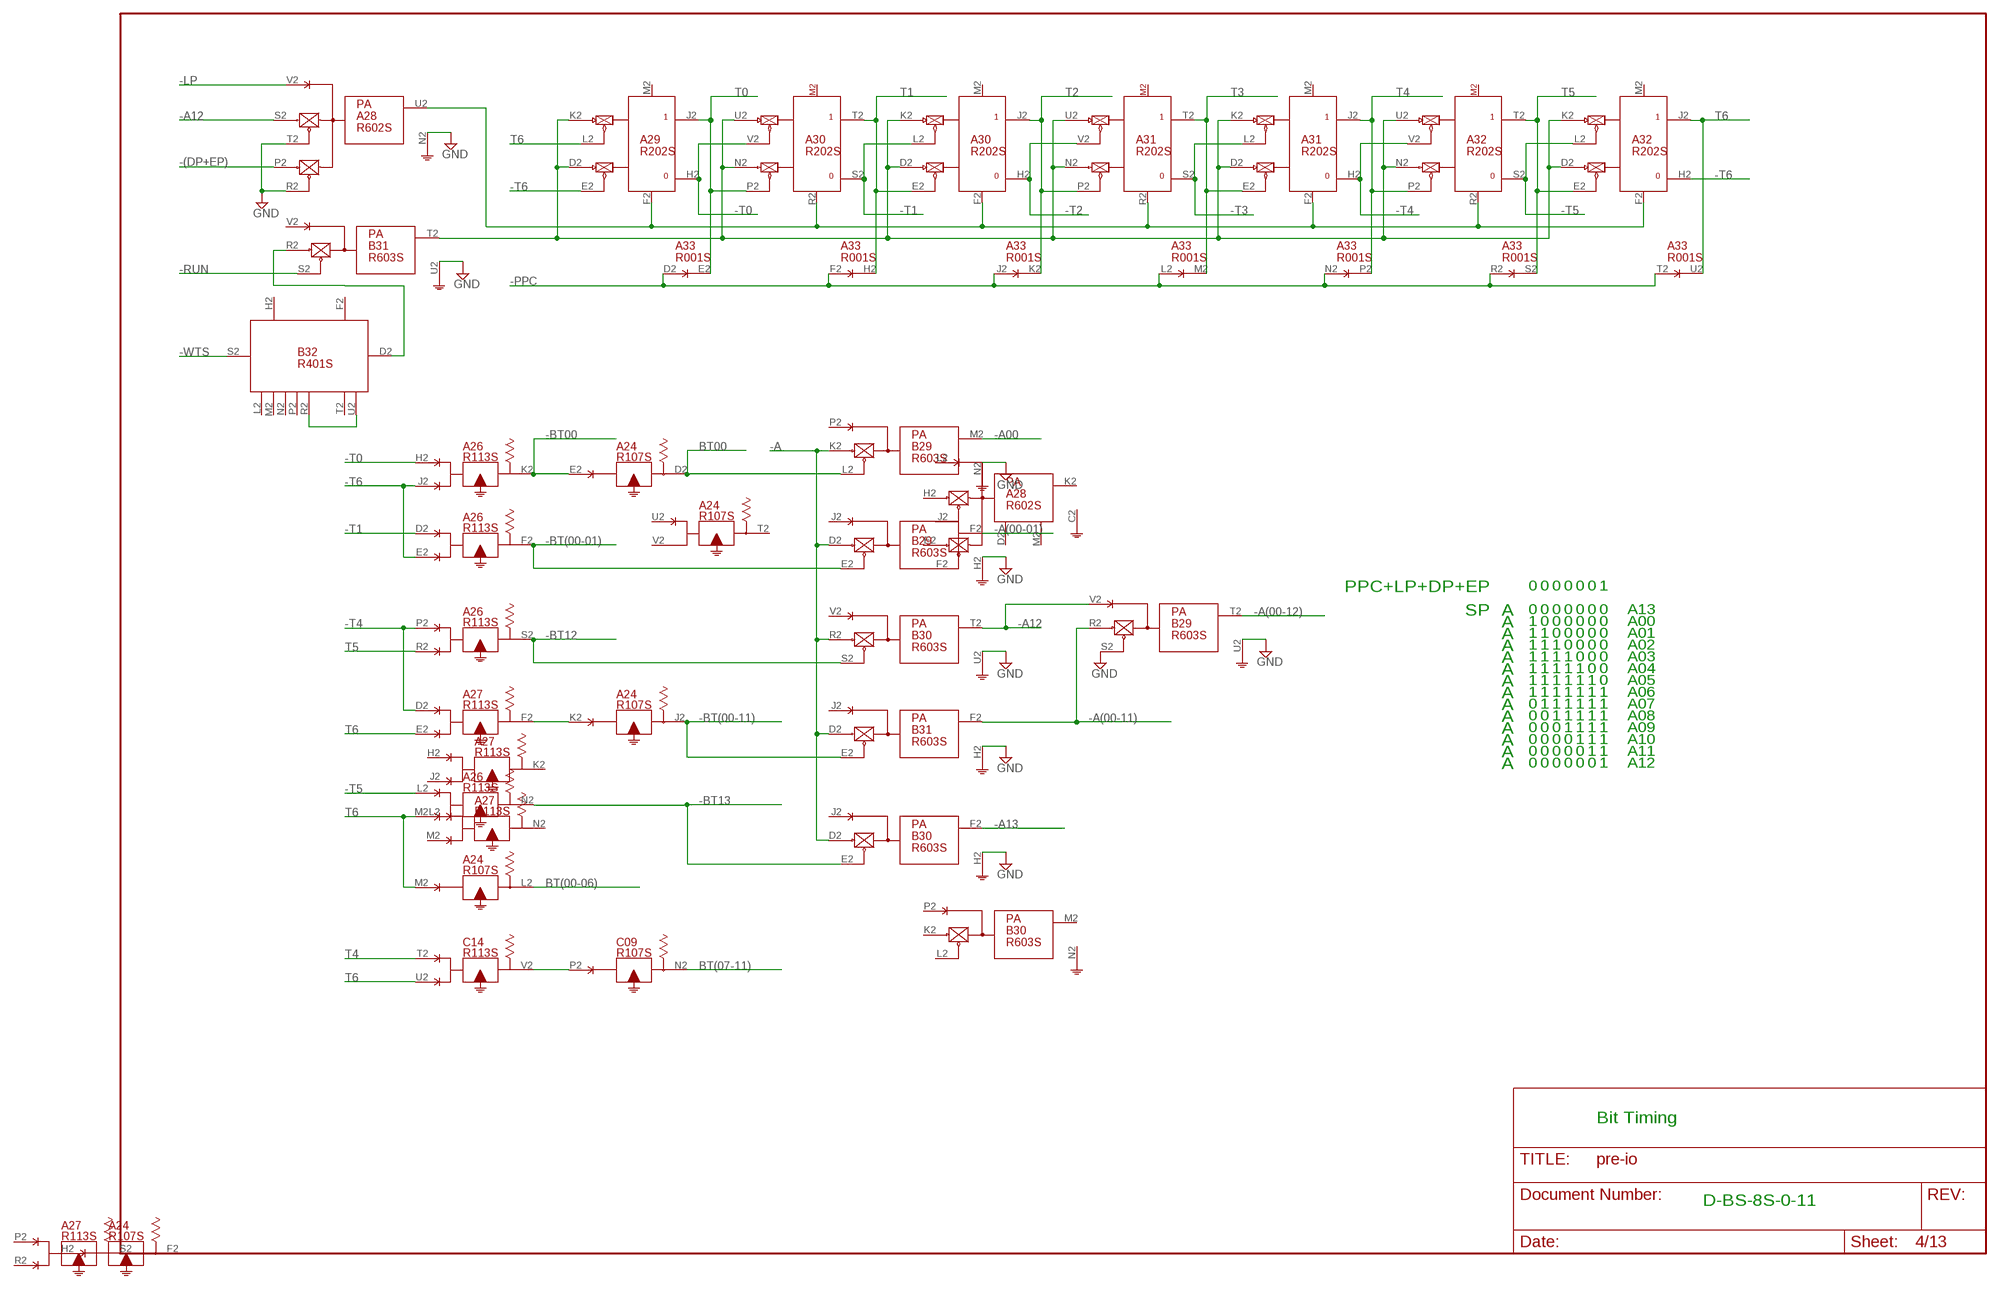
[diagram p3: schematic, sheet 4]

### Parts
A24  R107S  [H807S]
A26  R113S  [H807S]
A27  R113S  [H807S]
A29  R202S  [H807S]
A30  R202S  [H807S]
A31  R202S  [H807S]
A32  R202S  [H807S]
A33  R001S  [H807S]
B29  R603S  [H807S]
B31  R603S  [H807S]
B32  R401S  [H807S]
C09  R107S  [H807S]
C14  R113S  [H807S]

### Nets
-(DP+EP): A28.P2(U:E) ; also sheet 6,8
-A: B29.D2(F:PU0) B29.K2(M:PU0) B30.D2(F:PU0) B30.R2(T:PU0) B31.D2(F:PU0)
-A00: B29.M2(M:O) ; also sheet 3,5,9
-A12: A28.S2(U:H) B29.V2(T:I$1) B30.T2(T:O) ; also sheet 1,3,6,8
-A13: B30.F2(F:O) ; also sheet 1,5,6,7
-A(00-01): B29.F2(F:O) ; also sheet 3
-A(00-11): B29.R2(T:PU0) B31.F2(F:O) ; also sheet 1,3,5,7,9
-A(00-12): B29.T2(T:O) ; also sheet 7
-BT00: A24.E2(D:I$1) A26.K2(K:O$1)
-BT12: A26.S2(S:O$1) B30.S2(T:EN0) ; also sheet 7
-BT13: A26.N2(N:O$1) B30.E2(F:EN0)
-BT(00-01): A26.F2(F:O$1) B29.E2(F:EN0)
-BT(00-11): A24.J2(J:O$1) B31.E2(F:EN0)
-LP: A28.V2(U:L) ; also sheet 6,8
-PPC: A33.D2(E:D) A33.F2(H:D) A33.J2(K:D) A33.L2(M:D) A33.N2(P:D) A33.R2(S:D) A33.T2(U:D) ; also sheet 6,8
-RUN: B31.S2(T:EN0) ; also sheet 8
-T0: A26.H2(K:I$1) A29.H2 A30.V2(T:EN1)
-T1: A26.D2(F:I$1) A30.L2(J:EN1) A30.S2
-T2: A30.H2 A31.V2(T:EN1)
-T3: A31.L2(J:EN1) A31.S2
-T4: A26.P2(S:I$1) A27.D2(F:I$1) A31.H2 A32.V2(T:EN1)
-T5: A26.L2(N:I$1) A32.L2(J:EN1) A32.S2
-T6: A26.E2(F:I$2) A26.J2(K:I$2) A29.E2(J:EN0) A32.H2
-WTS: B32.S2(S) ; also sheet 1,6
BT00: A24.D2(D:O$1) B29.L2(M:EN0) ; also sheet 7,9
BT(00-06): A24.L2(L:O$1) ; also sheet 6
BT(07-11): C09.N2(N:O$1) ; also sheet 6
GND [Supply]: A28.N2(U:C) A28.R2(U:F) A28.T2(U:J) B29.H2(F:G) B29.N2(M:G) B29.S2(T:EN0) B29.U2(T:G) B30.H2(F:G) B30.U2(T:G) B31.H2(F:G) B31.U2(T:G) ; also sheet 1,2,3,5,6,7,8,9
N$77: A24.K2(J:I$1) A27.F2(F:O$1)
N$78: C09.P2(N:I$1) C14.V2(V:O$1)
N$80: A29.D2(J:PU0) A29.K2(J:PU1) A30.D2(J:PU0) A30.K2(J:PU1) A30.N2(T:PU0) A30.U2(T:PU1) A31.D2(J:PU0) A31.K2(J:PU1) A31.N2(T:PU0) A31.U2(T:PU1) A32.D2(J:PU0) A32.K2(J:PU1) A32.N2(T:PU0) A32.U2(T:PU1) B31.T2(T:O)
N$85: B31.R2(T:PU0) B32.D2(D)
N$88: B32.R2(R) B32.U2(U)
N$94: A28.U2(U:K) A29.F2(J:RESET) A30.F2(J:RESET) A30.R2(T:RESET) A31.F2(J:RESET) A31.R2(T:RESET) A32.F2(J:RESET) A32.R2(T:RESET)
T0: A29.J2 A30.P2(T:EN0) A33.E2(E:E)
T1: A30.E2(J:EN0) A30.T2 A33.H2(H:E)
T2: A30.J2 A31.P2(T:EN0) A33.K2(K:E)
T3: A31.E2(J:EN0) A31.T2 A33.M2(M:E)
T4: A31.J2 A32.P2(T:EN0) A33.P2(P:E) C14.T2(V:I$1)
T5: A26.R2(S:I$2) A32.E2(J:EN0) A32.T2 A33.S2(S:E)
T6: A24.M2(L:I$1) A26.M2(N:I$2) A27.E2(F:I$2) A29.L2(J:EN1) A32.J2 A33.U2(U:E) C14.U2(V:I$2)
Unconnected: A24.N2(N:O$1) A24.P2(N:I$1) A24.R2(R:O$1) A24.S2(R:I$1) A27.T2(V:I$1) A27.U2(V:I$2) A27.V2(V:O$1) A28.D2(K:D) A28.L2(K:L) A28.M2(K:M) A29.M2(J:SET) A30.M2(J:SET) A31.M2(J:SET) A32.M2(J:SET) B29.J2(F:I$1) B29.P2(M:I$1) B30.J2(F:I$1) B30.P2(M:I$1) B30.V2(T:I$1) B31.J2(F:I$1) B31.V2(T:I$1) B32.F2(F) B32.H2(H) B32.L2(L) B32.M2(M) B32.N2(N) B32.P2(P) B32.T2(T) C14.D2(F:I$1) C14.E2(F:I$2) C14.F2(F:O$1) C14.H2(K:I$1) C14.J2(K:I$2) C14.K2(K:O$1) C14.L2(N:I$1) C14.M2(N:I$2) C14.N2(N:O$1) C14.P2(S:I$1) C14.R2(S:I$2) C14.S2(S:O$1)

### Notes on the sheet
- PPC+LP+DP+EP | 0 | 0 | 0 | 0 | 0 | 0 | 1
- SP | A | 0 | 0 | 0 | 0 | 0 | 0 | 0 | A13
- A | 1 | 0 | 0 | 0 | 0 | 0 | 0 | A00
- A | 1 | 1 | 0 | 0 | 0 | 0 | 0 | A01
- A | 1 | 1 | 1 | 0 | 0 | 0 | 0 | A02
- A | 1 | 1 | 1 | 1 | 0 | 0 | 0 | A03
- A | 1 | 1 | 1 | 1 | 1 | 0 | 0 | A04
- A | 1 | 1 | 1 | 1 | 1 | 1 | 0 | A05
- A | 1 | 1 | 1 | 1 | 1 | 1 | 1 | A06
- A | 0 | 1 | 1 | 1 | 1 | 1 | 1 | A07
- A | 0 | 0 | 1 | 1 | 1 | 1 | 1 | A08
- A | 0 | 0 | 0 | 1 | 1 | 1 | 1 | A09
- A | 0 | 0 | 0 | 0 | 1 | 1 | 1 | A10
- A | 0 | 0 | 0 | 0 | 0 | 1 | 1 | A11
- A | 0 | 0 | 0 | 0 | 0 | 0 | 1 | A12
- Bit Timing
- D-BS-8S-0-11

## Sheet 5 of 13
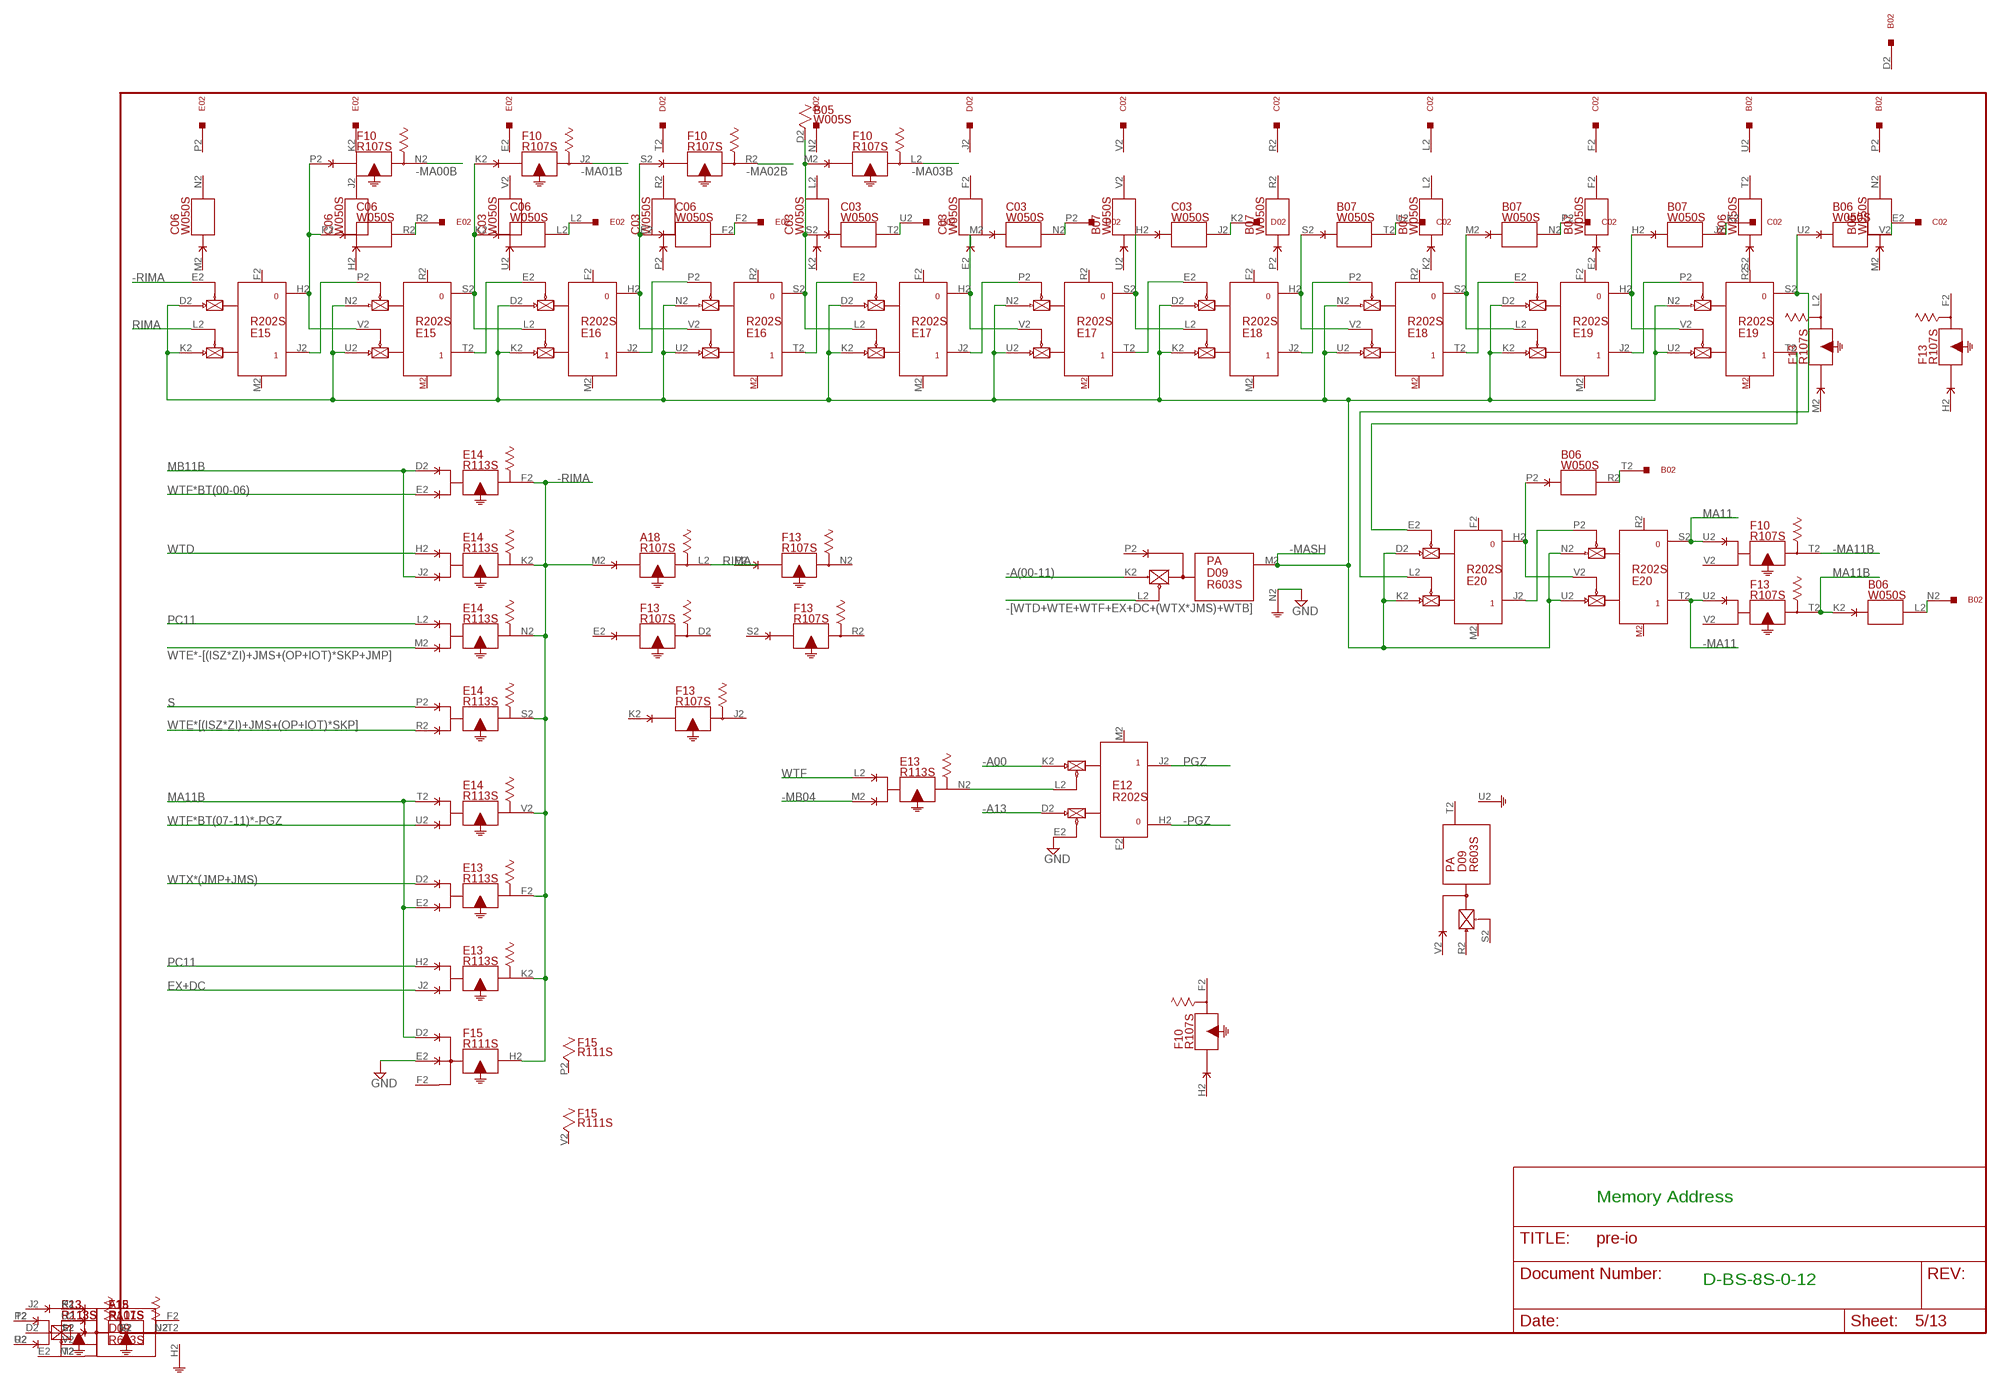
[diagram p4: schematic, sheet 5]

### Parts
A18  R107S  [H807S]
B05  W005S  [H807S]
E12  R202S  [H807S]
E13  R113S  [H807S]
E14  R113S  [H807S]
E15  R202S  [H807S]
E16  R202S  [H807S]
E17  R202S  [H807S]
E18  R202S  [H807S]
E19  R202S  [H807S]
E20  R202S  [H807S]
F15  R111S  [H807S]

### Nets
-[WTD+WTE+WTF+EX+DC+(WTX*JMS)+WTB]: D09.L2(M:EN0) ; also sheet 6
-A00: E12.K2(J:PU1) ; also sheet 3,4,9
-A13: E12.D2(J:PU0) ; also sheet 1,4,6,7
-A(00-11): D09.K2(M:PU0) ; also sheet 1,3,4,7,9
-MA00B: F10.N2(N:O$1) ; also sheet 6
-MA01B: F10.J2(J:O$1) ; also sheet 6
-MA02B: F10.R2(R:O$1) ; also sheet 6
-MA03B: F10.L2(L:O$1) ; also sheet 6
-MA11: E20.T2 F13.U2(T:I$1) ; also sheet 2
-MA11B: F10.T2(T:O$1)
-MASH: D09.M2(M:O) E15.D2(J:PU0) E15.K2(J:PU1) E15.N2(T:PU0) E15.U2(T:PU1) E16.D2(J:PU0) E16.K2(J:PU1) E16.N2(T:PU0) E16.U2(T:PU1) E17.D2(J:PU0) E17.K2(J:PU1) E17.N2(T:PU0) E17.U2(T:PU1) E18.D2(J:PU0) E18.K2(J:PU1) E18.N2(T:PU0) E18.U2(T:PU1) E19.D2(J:PU0) E19.K2(J:PU1) E19.N2(T:PU0) E19.U2(T:PU1) E20.D2(J:PU0) E20.K2(J:PU1) E20.N2(T:PU0) E20.U2(T:PU1)
-MB04: E13.M2(N:I$2) ; also sheet 1,2
-PGZ: E12.H2 ; also sheet 6
-RIMA: A18.M2(L:I$1) E13.F2(F:O$1) E13.K2(K:O$1) E14.F2(F:O$1) E14.K2(K:O$1) E14.N2(N:O$1) E14.S2(S:O$1) E14.V2(V:O$1) E15.E2(J:EN0) F15.H2(H:O$1)
EX+DC: E13.J2(K:I$2) ; also sheet 7,8,9
GND [Supply]: D09.N2(M:G) E12.E2(J:EN0) F15.E2(H:I$2) ; also sheet 1,2,3,4,6,7,8,9
MA11: E20.S2 F10.U2(T:I$1)
MA11B: B06.K2(L:I$1) E13.E2(F:I$2) E14.T2(V:I$1) F13.T2(T:O$1) F15.D2(H:I$1)
MB11B: E14.D2(F:I$1) E14.J2(K:I$2)
N$70: E15.J2 E15.P2(T:EN0)
N$81: C06.P2(R:I$1) E15.H2 E15.V2(T:EN1) F10.P2(N:I$1)
N$82: E12.L2(J:EN1) E13.N2(N:O$1)
N$83: C06.K2(L:I$1) E15.S2 E16.L2(J:EN1) F10.K2(J:I$1)
N$84: C06.E2(F:I$1) E16.H2 E16.V2(T:EN1) F10.S2(R:I$1)
N$86: B05.D2 C03.S2(T:I$1) E16.S2 E17.L2(J:EN1) F10.M2(L:I$1)
N$87: C03.M2(N:I$1) E17.H2 E17.V2(T:EN1)
N$89: C03.H2(J:I$1) E17.S2 E18.L2(J:EN1)
N$90: B07.S2(T:I$1) E18.H2 E18.V2(T:EN1)
N$91: E15.T2 E16.E2(J:EN0)
N$93: E16.J2 E16.P2(T:EN0)
N$95: C06.R2(R:O$1) E02.R2
N$96: E16.T2 E17.E2(J:EN0)
N$97: C06.L2(L:O$1) E02.L2
N$98: E17.J2 E17.P2(T:EN0)
N$99: E17.T2 E18.E2(J:EN0)
N$100: C06.F2(F:O$1) E02.F2
N$101: E18.J2 E18.P2(T:EN0)
N$102: B07.M2(N:I$1) E18.S2 E19.L2(J:EN1)
N$103: E18.T2 E19.E2(J:EN0)
N$104: C03.T2(T:O$1) D02.U2
N$105: E19.J2 E19.P2(T:EN0)
N$106: B07.H2(J:I$1) E19.H2 E19.V2(T:EN1)
N$107: B06.U2(V:I$1) E19.S2 E20.L2(J:EN1)
N$108: E19.T2 E20.E2(J:EN0)
N$109: C03.N2(N:O$1) D02.P2
N$110: B06.P2(R:I$1) E20.H2 E20.V2(T:EN1)
N$111: E20.J2 E20.P2(T:EN0)
N$112: C03.J2(J:O$1) D02.K2
N$113: B07.T2(T:O$1) C02.U2
N$114: B07.N2(N:O$1) C02.P2
N$115: B07.J2(J:O$1) C02.K2
N$116: B06.V2(V:O$1) C02.E2
N$117: B02.T2 B06.R2(R:O$1)
N$118: B02.N2 B06.L2(L:O$1)
PC11: E13.H2(K:I$1) E14.L2(N:I$1) ; also sheet 1,7
PGZ: E12.J2
RIMA: A18.L2(L:O$1) E15.L2(J:EN1)
S: E14.P2(S:I$1) ; also sheet 1,7
WTD: E14.H2(K:I$1) ; also sheet 6
WTE*-[(ISZ*ZI)+JMS+(OP+IOT)*SKP+JMP]: E14.M2(N:I$2) ; also sheet 6
WTE*[(ISZ*ZI)+JMS+(OP+IOT)*SKP]: E14.R2(S:I$2) ; also sheet 6
WTF: E13.L2(N:I$1) ; also sheet 1,3,6,8
WTF*BT(00-06): E14.E2(F:I$2) ; also sheet 6
WTF*BT(07-11)*-PGZ: E14.U2(V:I$2) ; also sheet 6
WTX*(JMP+JMS): E13.D2(F:I$1) ; also sheet 6
Unconnected: B05.E2 B05.F2 B05.H2 B05.J2 B05.K2 B05.L2 B05.M2 B05.N2 B05.P2 B05.R2 B05.S2 B05.T2 B05.U2 B05.V2 D09.J2(F:I$1) D09.P2(M:I$1) D09.V2(T:I$1) E15.F2(J:RESET) E15.M2(J:SET) E15.R2(T:RESET) E16.F2(J:RESET) E16.M2(J:SET) E16.R2(T:RESET) E17.F2(J:RESET) E17.M2(J:SET) E17.R2(T:RESET) E18.F2(J:RESET) E18.M2(J:SET) E18.R2(T:RESET) E19.F2(J:RESET) E19.M2(J:SET) E19.R2(T:RESET) E20.F2(J:RESET) E20.M2(J:SET) E20.R2(T:RESET) F10.V2(T:I$2) F15.J2

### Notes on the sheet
- Memory Address
- D-BS-8S-0-12

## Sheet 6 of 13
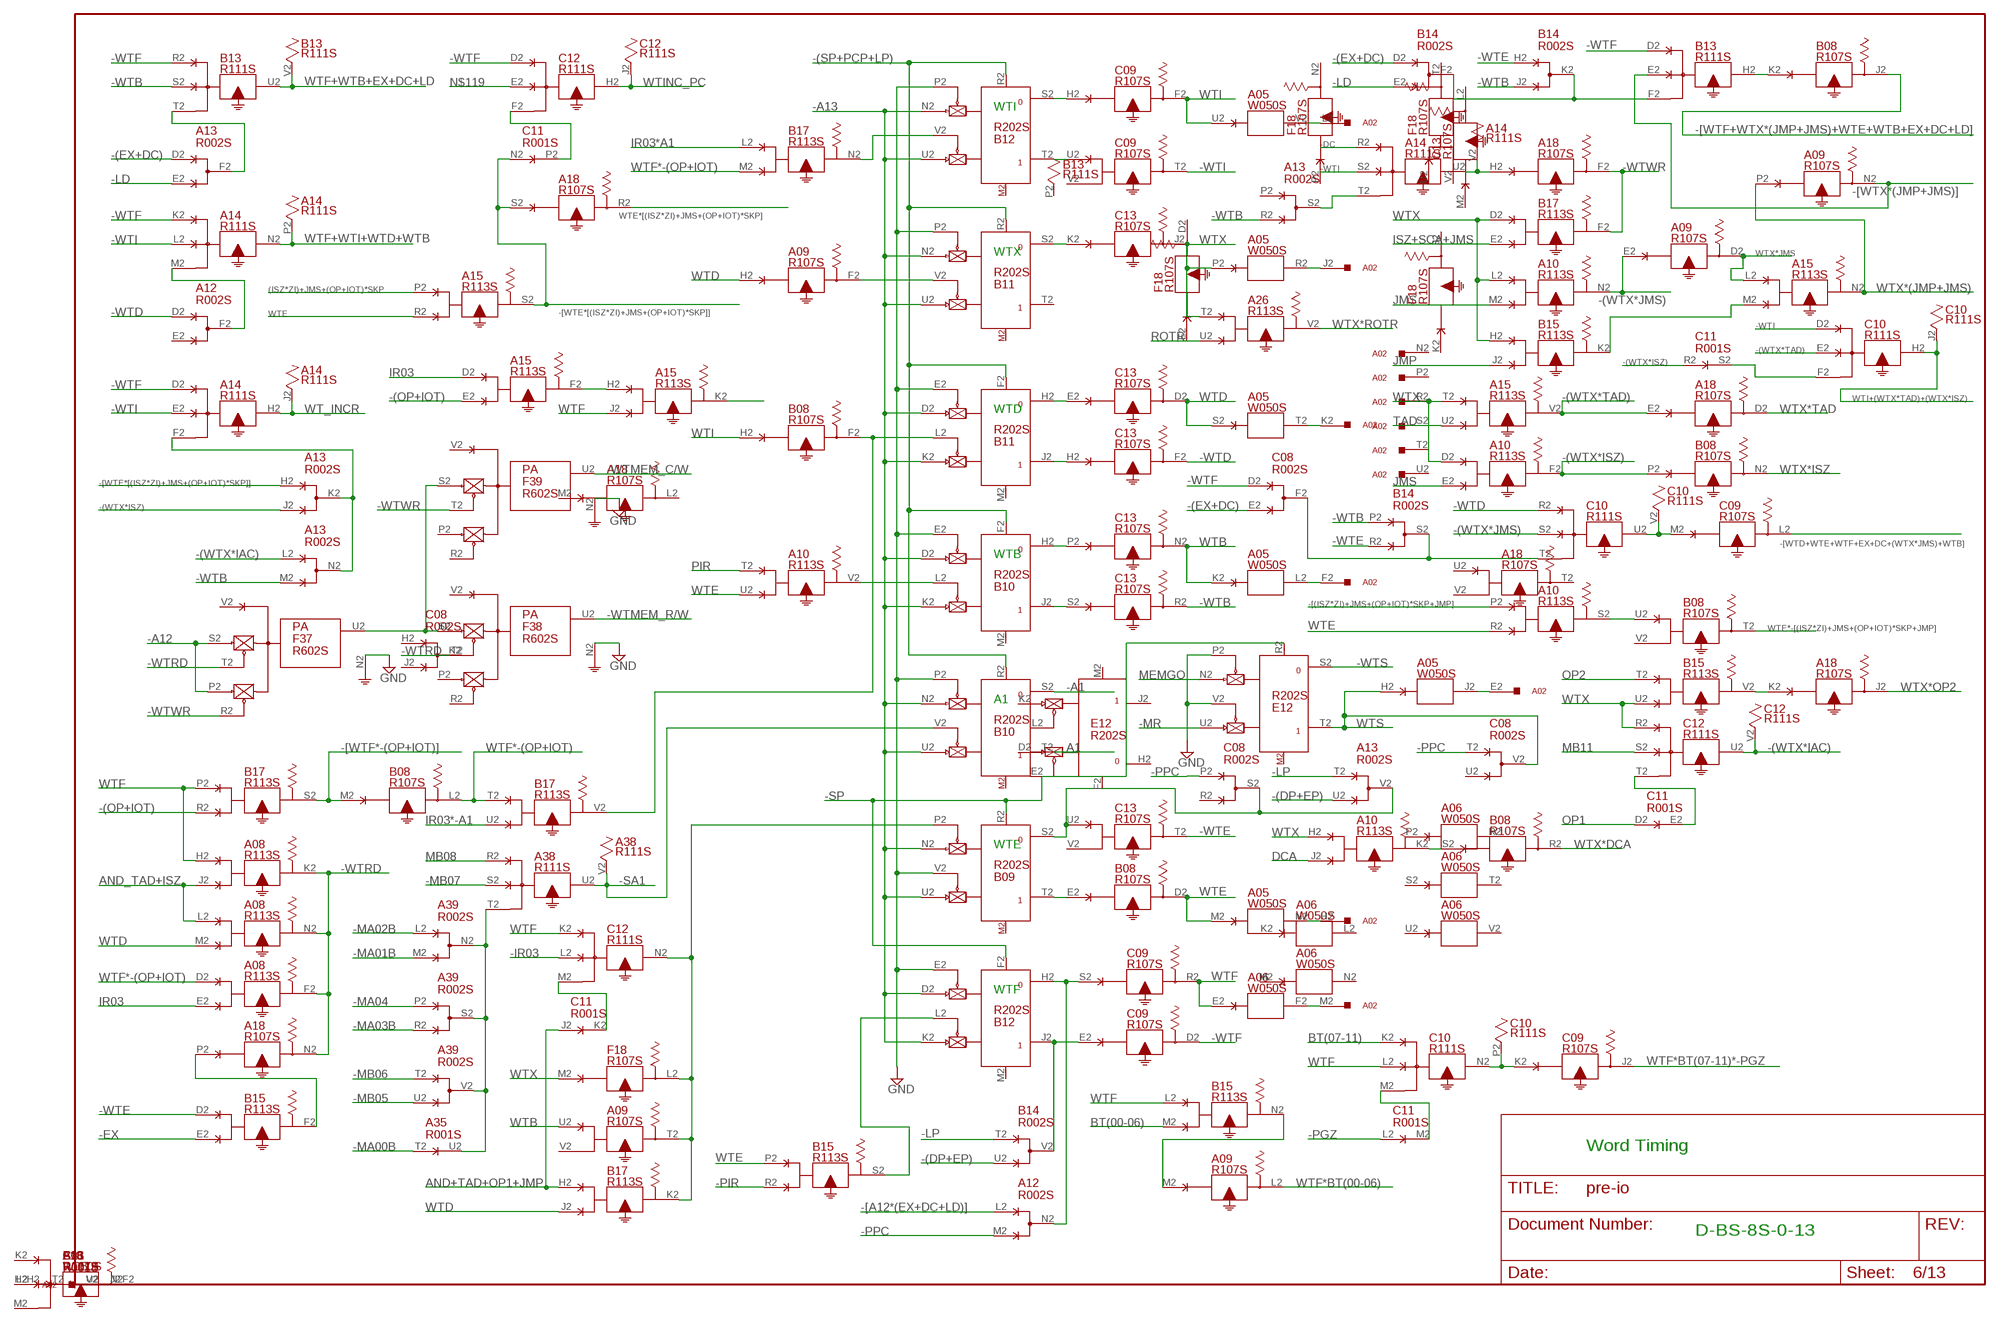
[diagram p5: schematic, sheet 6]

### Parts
A02  W023S  [H807S]
A05  W050S  [H807S]
A06  W050S  [H807S]
A08  R113S  [H807S]
A09  R107S  [H807S]
A10  R113S  [H807S]
A12  R002S  [H807S]
A13  R002S  [H807S]
A14  R111S  [H807S]
A15  R113S  [H807S]
A35  R001S  [H807S]
A38  R111S  [H807S]
A39  R002S  [H807S]
B08  R107S  [H807S]
B09  R202S  [H807S]
B10  R202S  [H807S]
B11  R202S  [H807S]
B12  R202S  [H807S]
B13  R111S  [H807S]
B14  R002S  [H807S]
B15  R113S  [H807S]
B17  R113S  [H807S]
C10  R111S  [H807S]
C11  R001S  [H807S]
C12  R111S  [H807S]
F37  R602S  [H807S]
F38  R602S  [H807S]
F39  R602S  [H807S]

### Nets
(ISZ*ZI)+JMS+(OP+IOT)*SKP: A15.P2(S:I$1)
-(DP+EP): A13.U2(V:E) B14.U2(V:E) ; also sheet 4,8
-(EX+DC): A13.D2(F:D) B14.D2(F:D) C08.E2(F:E) ; also sheet 8
-(OP+IOT): A15.E2(F:I$2) B17.R2(S:I$2) ; also sheet 1,9
-(SP+PCP+LP): B10.F2(J:RESET) B10.R2(T:RESET) B11.F2(J:RESET) B11.R2(T:RESET) B12.R2(T:RESET) ; also sheet 8,9
-(WTX*IAC): A13.L2(N:D) C12.U2(U:O$1) C12.V2
-(WTX*ISZ): A10.F2(F:O$1) A13.J2(K:E) B08.P2(N:I$1) C11.R2(S:D) ; also sheet 7
-(WTX*JMS): A09.E2(D:I$1) A10.N2(N:O$1) C10.S2(U:I$2)
-(WTX*TAD): A15.V2(V:O$1) A18.E2(D:I$1) C10.E2(H:I$2)
-[(ISZ*ZI)+JMS+(OP+IOT)*SKP+JMP]: A10.P2(S:I$1)
-[A12*(EX+DC+LD)]: A12.L2(N:D) ; also sheet 8
-[WTD+WTE+WTF+EX+DC+(WTX*JMS)+WTB]: C09.L2(L:O$1) ; also sheet 5
-[WTE*[(ISZ*ZI)+JMS+(OP+IOT)*SKP]]: A13.H2(K:D) A15.S2(S:O$1) A18.S2(R:I$1) C11.N2(P:D)
-[WTF*-(OP+IOT)]: B08.M2(L:I$1) B17.S2(S:O$1)
-[WTF+WTX*(JMP+JMS)+WTE+WTB+EX+DC+LD]: B08.J2(J:O$1)
-[WTX*(JMP+JMS)]: A09.N2(N:O$1) B13.E2(H:I$2)
-A1: B10.S2 ; also sheet 9
-A12: F37.P2(U:E) F37.S2(U:H) ; also sheet 1,3,4,8
-A13: B09.N2(T:PU0) B09.U2(T:PU1) B10.D2(J:PU0) B10.K2(J:PU1) B10.N2(T:PU0) B10.U2(T:PU1) B11.D2(J:PU0) B11.K2(J:PU1) B11.N2(T:PU0) B11.U2(T:PU1) B12.D2(J:PU0) B12.K2(J:PU1) B12.N2(T:PU0) B12.U2(T:PU1) ; also sheet 1,4,5,7
-DC: A14.R2(U:I$1) ; also sheet 8
-EX: B15.E2(F:I$2) ; also sheet 8
-IR03: C12.L2(N:I$2) ; also sheet 9
-LD: A13.E2(F:E) B14.E2(F:E) ; also sheet 8
-LP: A13.T2(V:D) B14.T2(V:D) ; also sheet 4,8
-MA00B: A35.T2(U:D) ; also sheet 5
-MA01B: A39.M2(N:E) ; also sheet 5
-MA02B: A39.L2(N:D) ; also sheet 5
-MA03B: A39.R2(S:E) ; also sheet 5
-MA04: A39.P2(S:D) ; also sheet 2
-MB05: A39.U2(V:E) ; also sheet 1,2
-MB06: A39.T2(V:D) ; also sheet 1,2,7
-MB07: A38.S2(U:I$2) ; also sheet 1,2
-MR: E12.U2(T:PU1)
-PGZ: C11.L2(M:D) ; also sheet 5
-PIR: B15.R2(S:I$2)
-PPC: A12.M2(N:E) C08.P2(S:D) C08.T2(V:D) ; also sheet 4,8
-SA1: A38.U2(U:O$1) A38.V2 B10.V2(T:EN1)
-SP: B09.R2(T:RESET) B12.F2(J:RESET) E12.R2(T:RESET) ; also sheet 1,8
-WTB: A13.M2(N:E) A13.R2(S:E) B13.S2(U:I$2) B14.J2(K:E) B14.P2(S:D) C13.R2(R:O$1) ; also sheet 9
-WTD: A12.D2(F:D) C10.R2(U:I$1) C13.F2(F:O$1)
-WTE: B14.H2(K:D) B14.R2(S:E) B15.D2(F:I$1) C13.T2(T:O$1) ; also sheet 3
-WTF: A14.D2(H:I$1) A14.K2(N:I$1) B13.D2(H:I$1) B13.R2(U:I$1) C08.D2(F:D) C09.D2(D:O$1) C12.D2(H:I$1) ; also sheet 7,9
-WTI: A14.E2(H:I$2) A14.L2(N:I$2) A14.S2(U:I$2) C09.T2(T:O$1) C10.D2(H:I$1)
-WTMEM_C/W: F39.U2(U:K)
-WTMEM_R/W: F38.U2(U:K)
-WTRD: A08.F2(F:O$1) A08.K2(K:O$1) A08.N2(N:O$1) A18.N2(N:O$1) F37.T2(U:J) F38.T2(U:J)
-WTS: E12.S2 ; also sheet 1,4
-WTWR: A18.F2(F:O$1) B17.F2(F:O$1) F37.R2(U:F) F39.T2(U:J) ; also sheet 1
A1: B10.T2 ; also sheet 9
AND+TAD+OP1+JMP: B17.H2(K:I$1) C11.J2(K:D) ; also sheet 9
AND_TAD+ISZ: A08.J2(K:I$2) A08.L2(N:I$1)
BT(00-06): B15.M2(N:I$2) ; also sheet 4
BT(07-11): C10.K2(N:I$1) ; also sheet 4
DCA: A10.J2(K:I$2) ; also sheet 9
GND [Supply]: B09.V2(T:EN1) B10.E2(J:EN0) B10.P2(T:EN0) B11.E2(J:EN0) B11.P2(T:EN0) B12.E2(J:EN0) B12.P2(T:EN0) E12.P2(T:EN0) E12.V2(T:EN1) F37.N2(U:C) F38.N2(U:C) F39.N2(U:C) ; also sheet 1,2,3,4,5,7,8,9
IR03: A08.E2(F:I$2) A15.D2(F:I$1) ; also sheet 9
IR03*-A1: B17.U2(V:I$2) ; also sheet 9
IR03*A1: B17.L2(N:I$1) ; also sheet 9
ISZ+SCA+JMS: B17.E2(F:I$2)
JMP: B15.J2(K:I$2) ; also sheet 9
JMS: A10.E2(F:I$2) A10.M2(N:I$2) ; also sheet 9
MB08: A38.R2(U:I$1) ; also sheet 1,3,9
MB11: C12.S2(U:I$2) ; also sheet 1,7,9
MEMGO: E12.N2(T:PU0)
N$92: A13.F2(F:F) B13.T2(U:I$3)
N$119: C12.E2(H:I$2)
N$120: C11.P2(P:E) C12.F2(H:I$3)
N$121: A13.K2(K:F) A13.N2(N:F) A14.F2(H:I$3)
N$122: A15.F2(F:O$1) A15.H2(K:I$1)
N$123: A15.K2(K:O$1)
N$124: F37.U2(U:K) F38.S2(U:H) F39.S2(U:H)
N$125: A12.F2(F:F) A14.M2(N:I$3)
N$126: A35.U2(U:E) A38.T2(U:I$3) A39.N2(N:F) A39.S2(S:F) A39.V2(V:F)
N$127: C11.K2(K:E) C12.M2(N:I$3)
N$128: A18.P2(N:I$1) B15.F2(F:O$1)
N$129: B12.S2 C09.H2(F:I$1)
N$130: B12.T2 C09.U2(T:I$1)
N$131: B11.S2 C13.K2(J:I$1)
N$132: B11.H2 C13.E2(D:I$1)
N$133: B11.J2 C13.H2(F:I$1)
N$134: B10.H2 C13.P2(N:I$1)
N$135: B10.J2 C13.S2(R:I$1)
N$136: B12.J2 B14.V2(V:F) C09.E2(D:I$1)
N$137: A09.T2(T:O$1) B09.P2(T:EN0) B17.K2(K:O$1) C12.N2(N:O$1) F18.L2(L:O$1)
N$138: A10.V2(V:O$1) B10.L2(J:EN1)
N$139: B08.F2(F:O$1) B11.L2(J:EN1) B17.V2(V:O$1)
N$140: A09.F2(F:O$1) B11.V2(T:EN1)
N$141: B12.V2(T:EN1) B17.N2(N:O$1)
N$142: B08.E2(D:I$1) B09.T2
N$143: A13.V2(V:F) B09.S2 C08.S2(S:F) C13.U2(T:I$1)
N$144: A12.N2(N:F) B12.H2 C09.S2(R:I$1)
N$145: A02.M2 A06.F2(F:O$1)
N$146: A02.H2 A05.N2(N:O$1)
N$147: A02.F2 A05.L2(L:O$1)
N$148: B12.L2(J:EN1) B15.S2(S:O$1)
N$149: A02.L2 A05.V2(V:O$1)
N$150: A02.J2 A05.R2(R:O$1)
N$151: A02.K2 A05.T2(T:O$1)
N$152: A14.U2(U:O$1) A14.V2 A18.H2(F:I$1)
N$153: A15.M2(N:I$2) B15.K2(K:O$1)
N$154: A13.S2(S:F) A14.T2(U:I$3)
N$155: B08.K2(J:I$1) B13.H2(H:O$1)
N$156: B13.F2(H:I$3) B14.F2(F:F) B14.K2(K:F)
N$157: B14.S2(S:F) C08.F2(F:F) C10.T2(U:I$3)
N$158: C09.M2(L:I$1) C10.U2(U:O$1) C10.V2
N$159: C10.F2(H:I$3) C11.S2(S:E)
N$160: A02.E2 A05.J2(J:O$1)
N$161: A10.S2(S:O$1) B08.U2(T:I$1)
N$162: A09.M2(L:I$1) B15.N2(N:O$1)
N$163: C10.M2(N:I$3) C11.M2(M:E)
N$164: C09.K2(J:I$1) C10.N2(N:O$1) C10.P2
N$166: A10.K2(K:O$1) B08.S2(R:I$1)
N$168: C11.E2(E:E) C12.T2(U:I$3)
N$173: A18.K2(J:I$1) B15.V2(V:O$1)
OP1: C11.D2(E:D) ; also sheet 7,9
OP2: B15.T2(V:I$1) ; also sheet 3,7,8,9
PIR: A10.T2(V:I$1)
ROTR: A26.U2(V:I$2) ; also sheet 9
TAD: A15.U2(V:I$2) ; also sheet 9
WT_INCR: A14.H2(H:O$1) A14.J2
WTB: A05.K2(L:I$1) A09.U2(T:I$1) C13.N2(N:O$1) ; also sheet 1
WTD: A05.S2(T:I$1) A08.M2(N:I$2) A09.H2(F:I$1) B17.J2(K:I$2) C13.D2(D:O$1) ; also sheet 5
WTE: A05.M2(N:I$1) A10.R2(S:I$2) A10.U2(V:I$2) A15.R2(S:I$2) B08.D2(D:O$1) B15.P2(S:I$1) ; also sheet 1,3,8
WTE*-[(ISZ*ZI)+JMS+(OP+IOT)*SKP+JMP]: B08.T2(T:O$1) ; also sheet 5
WTE*[(ISZ*ZI)+JMS+(OP+IOT)*SKP]: A18.R2(R:O$1) ; also sheet 5
WTF: A06.E2(F:I$1) A08.H2(K:I$1) A15.J2(K:I$2) B15.L2(N:I$1) B17.P2(S:I$1) C09.R2(R:O$1) C10.L2(N:I$2) C12.K2(N:I$1) ; also sheet 1,3,5,8
WTF*-(OP+IOT): A08.D2(F:I$1) B08.L2(L:O$1) B17.M2(N:I$2) B17.T2(V:I$1)
WTF*BT(00-06): A09.L2(L:O$1) ; also sheet 5
WTF*BT(07-11)*-PGZ: C09.J2(J:O$1) ; also sheet 5
WTF+WTB+EX+DC+LD: B13.U2(U:O$1) B13.V2
WTF+WTI+WTD+WTB: A14.N2(N:O$1) A14.P2 ; also sheet 1
WTI: A05.U2(V:I$1) B08.H2(F:I$1) C09.F2(F:O$1) ; also sheet 1
WTI+(WTX*TAD)+(WTX*ISZ): C10.H2(H:O$1) C10.J2 ; also sheet 7
WTINC_PC: C12.H2(H:O$1) C12.J2
WTS: A05.H2(J:I$1) C08.V2(V:F) E12.T2 ; also sheet 8
WTX: A05.P2(R:I$1) A10.D2(F:I$1) A10.H2(K:I$1) A10.L2(N:I$1) A15.T2(V:I$1) A26.T2(V:I$1) B15.H2(K:I$1) B15.U2(V:I$2) B17.D2(F:I$1) C12.R2(U:I$1) C13.J2(J:O$1) F18.M2(L:I$1) ; also sheet 1,3,7
WTX*(JMP+JMS): A09.P2(N:I$1) A15.N2(N:O$1) ; also sheet 5
WTX*DCA: B08.R2(R:O$1) ; also sheet 1
WTX*ISZ: B08.N2(N:O$1) ; also sheet 1
WTX*JMS: A09.D2(D:O$1) A15.L2(N:I$1) ; also sheet 1
WTX*OP2: A18.J2(J:O$1)
WTX*ROTR: A26.V2(V:O$1)
WTX*TAD: A18.D2(D:O$1) ; also sheet 7
Unconnected: A02.A2 A02.B2 A02.C2 A08.P2(S:I$1) A08.R2(S:I$2) A08.S2(S:O$1) A08.T2(V:I$1) A08.U2(V:I$2) A08.V2(V:O$1) A09.J2(J:O$1) A09.K2(J:I$1) A09.R2(R:O$1) A09.S2(R:I$1) A09.V2(T:I$2) A12.E2(F:E) A12.H2(K:D) A12.J2(K:E) A12.K2(K:F) A12.P2(S:D) A12.R2(S:E) A12.S2(S:F) A13.P2(S:D) A35.D2(E:D) A35.E2(E:E) A38.D2(H:I$1) A38.E2(H:I$2) A38.F2(H:I$3) A38.H2(H:O$1) A38.J2 A38.K2(N:I$1) A38.L2(N:I$2) A38.M2(N:I$3) A38.N2(N:O$1) A38.P2 A39.D2(F:D) A39.E2(F:E) A39.F2(F:F) A39.H2(K:D) A39.J2(K:E) A39.K2(K:F) B08.V2(T:I$2) B10.M2(J:SET) B11.M2(J:SET) B11.T2 B12.M2(J:SET) B13.J2 C08.R2(S:E) C08.U2(V:E) C09.V2(T:I$2) C11.F2(H:D) C11.H2(H:E) C12.P2 C13.V2(T:I$2) E12.F2(J:RESET) E12.M2(J:SET) F37.D2(K:D) F37.E2(K:E) F37.F2(K:F) F37.H2(K:H) F37.J2(K:J) F37.K2(K:K) F37.L2(K:L) F37.M2(K:M) F37.V2(U:L) F38.D2(K:D) F38.E2(K:E) F38.F2(K:F) F38.H2(K:H) F38.J2(K:J) F38.K2(K:K) F38.L2(K:L) F38.M2(K:M) F38.P2(U:E) F38.R2(U:F) F38.V2(U:L) F39.D2(K:D) F39.E2(K:E) F39.F2(K:F) F39.H2(K:H) F39.J2(K:J) F39.K2(K:K) F39.L2(K:L) F39.M2(K:M) F39.P2(U:E) F39.R2(U:F) F39.V2(U:L)

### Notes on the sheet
- WTI
- WTX
- WTD
- WTB
- A1
- WTE
- WTF
- Word Timing
- D-BS-8S-0-13

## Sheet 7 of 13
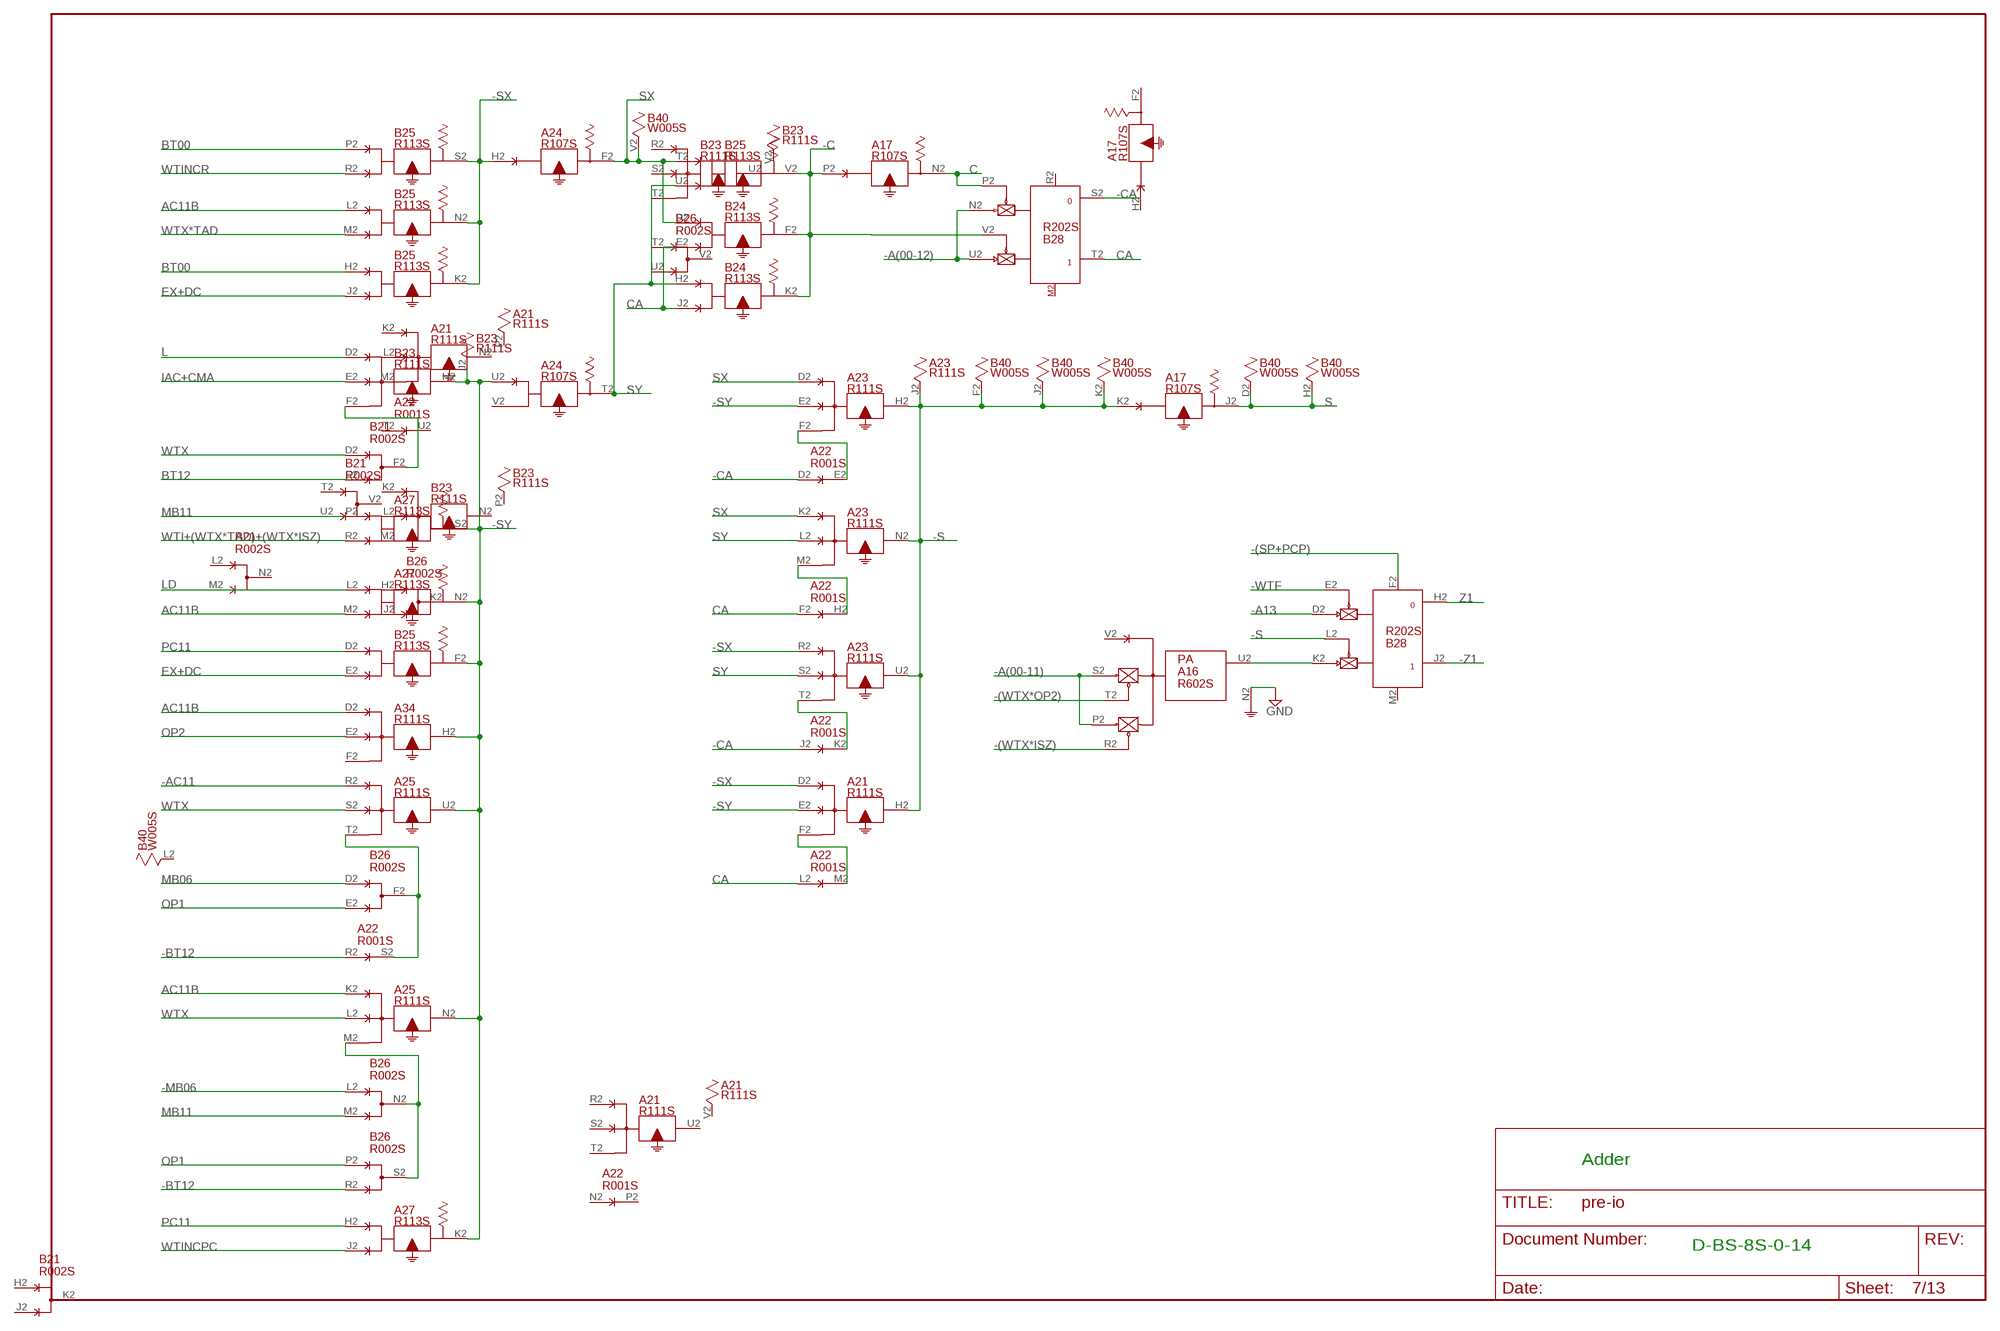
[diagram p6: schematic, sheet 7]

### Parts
A16  R602S  [H807S]
A23  R111S  [H807S]
A25  R111S  [H807S]
A34  R111S  [H807S]
B21  R002S  [H807S]
B24  R113S  [H807S]
B25  R113S  [H807S]
B28  R202S  [H807S]

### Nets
-(SP+PCP): B28.F2(J:RESET) ; also sheet 1,3,8
-(WTX*ISZ): A16.R2(U:F) ; also sheet 6
-(WTX*OP2): A16.T2(U:J) ; also sheet 3
-A13: B28.D2(J:PU0) ; also sheet 1,4,5,6
-A(00-11): A16.P2(U:E) A16.S2(U:H) ; also sheet 1,3,4,5,9
-A(00-12): B28.N2(T:PU0) B28.U2(T:PU1) ; also sheet 4
-AC11: A25.R2(U:I$1)
-BT12: A22.R2(S:D) B26.R2(S:E) ; also sheet 4
-C: A17.P2(N:I$1) B24.F2(F:O$1) B24.K2(K:O$1) B25.V2(V:O$1) B28.V2(T:EN1)
-CA: A22.D2(E:D) A22.J2(K:D) B28.S2
-MB06: B26.L2(N:D) ; also sheet 1,2,6
-S: A17.K2(J:I$1) A21.H2(H:O$1) A23.H2(H:O$1) A23.J2 A23.N2(N:O$1) A23.U2(U:O$1) B28.L2(J:EN1) B40.F2 B40.J2 B40.K2
-SX: A21.D2(H:I$1) A23.R2(U:I$1) A24.H2(F:I$1) B25.K2(K:O$1) B25.N2(N:O$1) B25.S2(S:O$1)
-SY: A21.E2(H:I$2) A23.E2(H:I$2) A24.U2(T:I$1) A25.N2(N:O$1) A25.U2(U:O$1) A27.K2(K:O$1) A27.N2(N:O$1) A27.S2(S:O$1) A34.H2(H:O$1) B23.H2(H:O$1) B23.J2 B25.F2(F:O$1)
-WTF: B28.E2(J:EN0) ; also sheet 6,9
-Z1: B28.J2
AC11B: A25.K2(N:I$1) A27.M2(N:I$2) A34.D2(H:I$1) B25.L2(N:I$1) ; also sheet 1
BT00: B25.H2(K:I$1) B25.P2(S:I$1) ; also sheet 4,9
BT12: B21.E2(F:E)
C: A17.N2(N:O$1) B28.P2(T:EN0)
CA: A22.F2(H:D) A22.L2(M:D) B24.E2(F:I$2) B24.J2(K:I$2) B28.T2
EX+DC: B25.E2(F:I$2) B25.J2(K:I$2) ; also sheet 5,8,9
GND [Supply]: A16.N2(U:C) ; also sheet 1,2,3,4,5,6,8,9
IAC+CMA: B23.E2(H:I$2) ; also sheet 9
L: B23.D2(H:I$1) ; also sheet 3
LD: A27.L2(N:I$1) ; also sheet 8
MB06: B26.D2(F:D) ; also sheet 1,3,9
MB11: A27.P2(S:I$1) B26.M2(N:E) ; also sheet 1,6,9
N$165: B21.F2(F:F) B23.F2(H:I$3)
N$167: A16.U2(U:K) B28.K2(J:PU1)
N$169: A22.S2(S:E) A25.T2(U:I$3) B26.F2(F:F)
N$170: A22.E2(E:E) A23.F2(H:I$3)
N$171: A25.M2(N:I$3) B26.N2(N:F) B26.S2(S:F)
N$172: A22.H2(H:E) A23.M2(N:I$3)
N$174: A22.K2(K:E) A23.T2(U:I$3)
N$175: A21.F2(H:I$3) A22.M2(M:E)
OP1: B26.E2(F:E) B26.P2(S:D) ; also sheet 6,9
OP2: A34.E2(H:I$2) ; also sheet 3,6,8,9
PC11: A27.H2(K:I$1) B25.D2(F:I$1) ; also sheet 1,5
S: A17.J2(J:O$1) B40.D2 B40.H2 ; also sheet 1,5
SX: A23.D2(H:I$1) A23.K2(N:I$1) A24.F2(F:O$1) B24.D2(F:I$1) B25.T2(V:I$1) B40.V2
SY: A23.L2(N:I$2) A23.S2(U:I$2) A24.T2(T:O$1) B24.H2(K:I$1) B25.U2(V:I$2)
WTI+(WTX*TAD)+(WTX*ISZ): A27.R2(S:I$2) ; also sheet 6
WTINCPC: A27.J2(K:I$2)
WTINCR: B25.R2(S:I$2)
WTX: A25.L2(N:I$2) A25.S2(U:I$2) B21.D2(F:D) ; also sheet 1,3,6
WTX*TAD: B25.M2(N:I$2) ; also sheet 6
Z1: B28.H2 ; also sheet 9
Unconnected: A16.D2(K:D) A16.E2(K:E) A16.F2(K:F) A16.H2(K:H) A16.J2(K:J) A16.K2(K:K) A16.L2(K:L) A16.M2(K:M) A16.V2(U:L) A23.P2 A23.V2 A24.V2(T:I$2) A25.D2(H:I$1) A25.E2(H:I$2) A25.F2(H:I$3) A25.H2(H:O$1) A25.J2 A25.P2 A25.V2 A34.J2 A34.R2(U:I$1) A34.S2(U:I$2) A34.T2(U:I$3) A34.U2(U:O$1) A34.V2 B24.L2(N:I$1) B24.M2(N:I$2) B24.N2(N:O$1) B24.P2(S:I$1) B24.R2(S:I$2) B24.S2(S:O$1) B26.U2(V:E) B28.M2(J:SET) B28.R2(T:RESET)

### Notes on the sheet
- Adder
- D-BS-8S-0-14

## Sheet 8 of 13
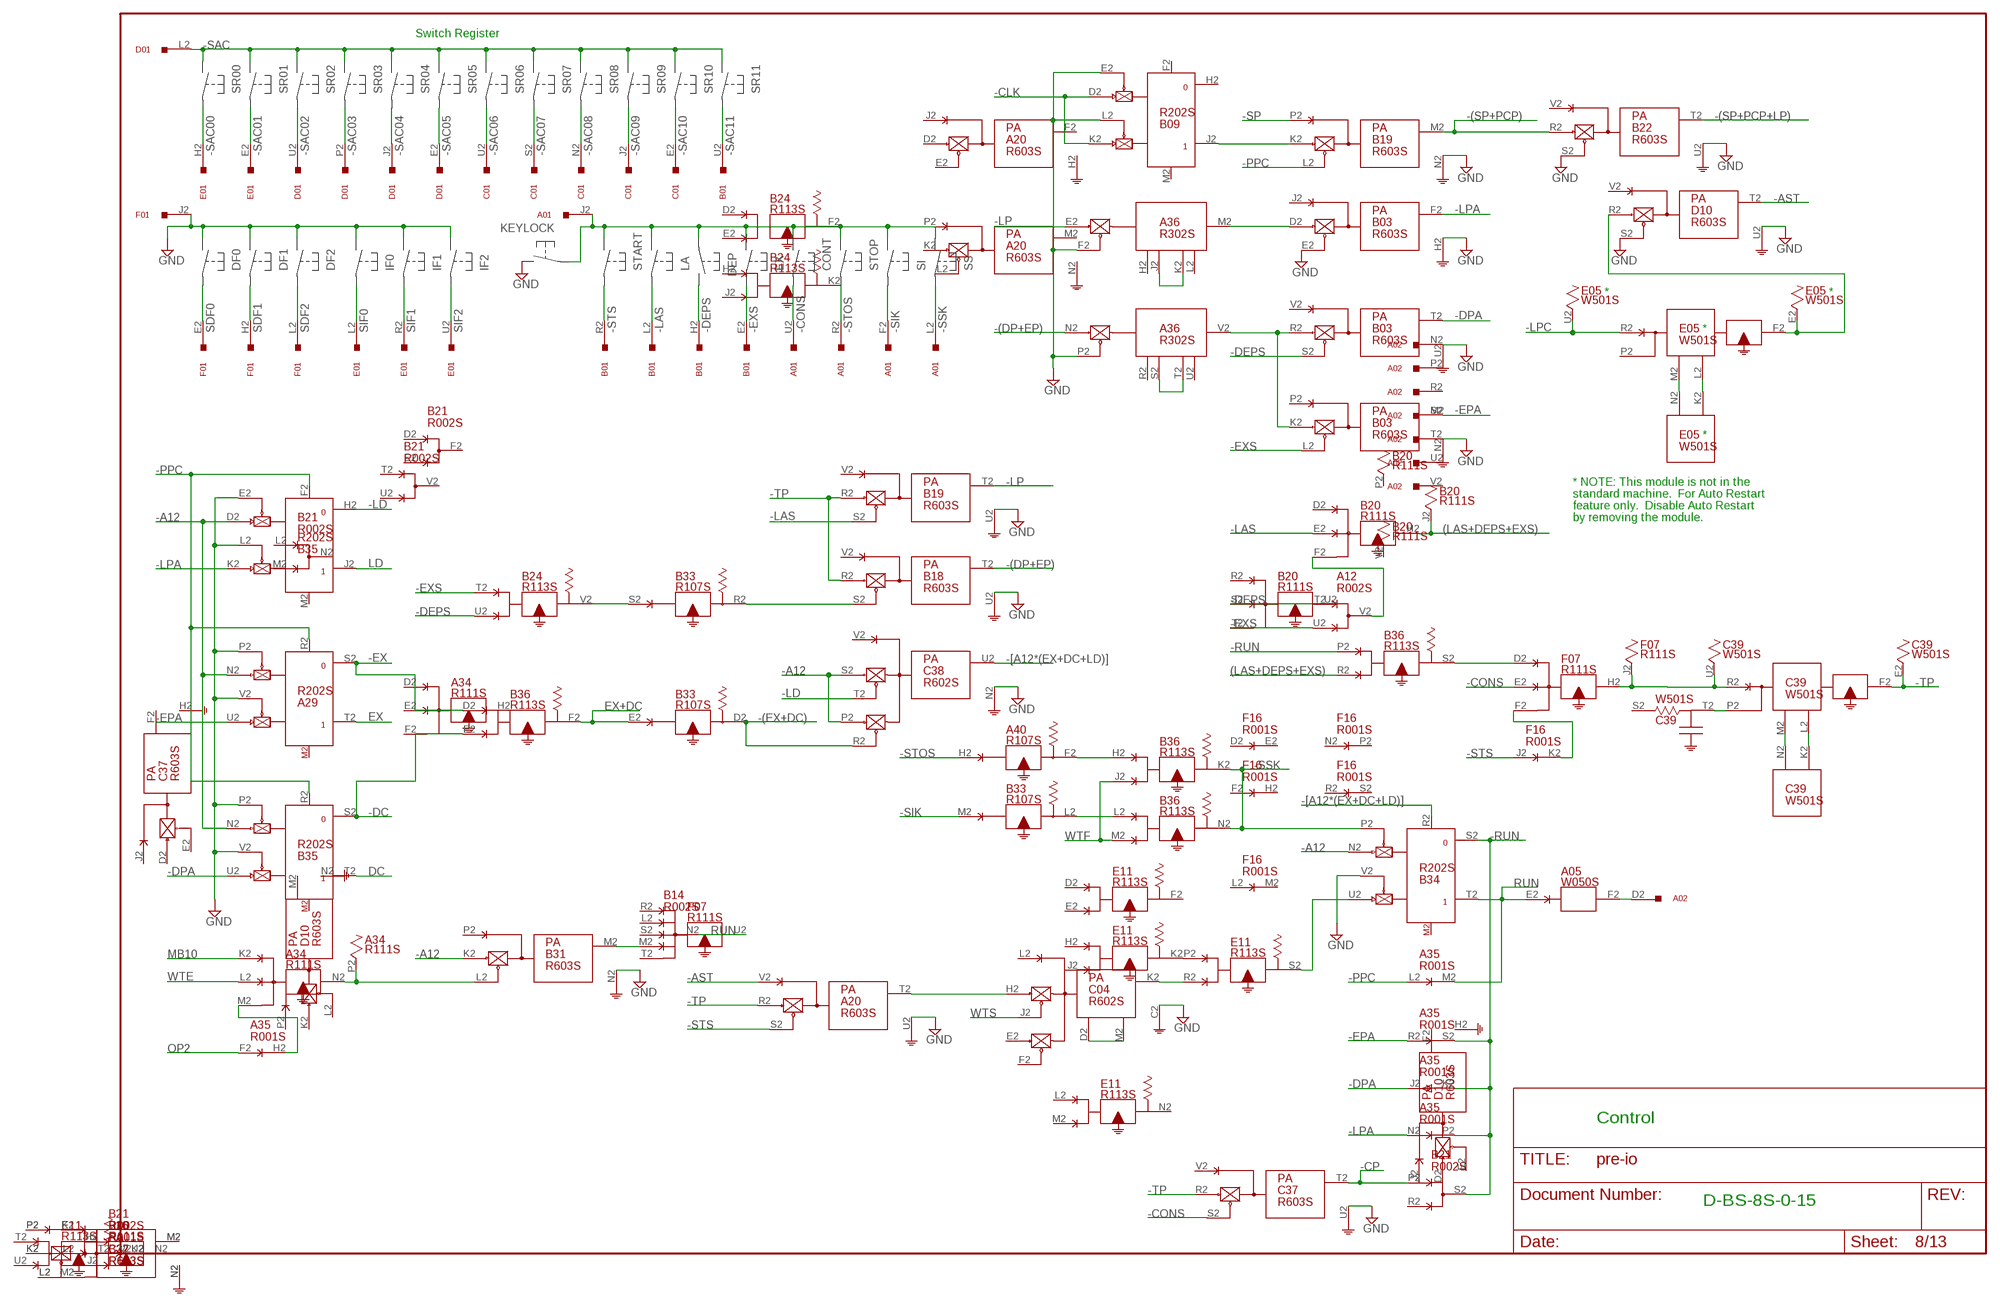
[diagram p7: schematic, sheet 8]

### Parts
A01  W023S  [H807S]
A36  R302S  [H807S]
A40  R107S  [H807S]
B01  W023S  [H807S]
B03  R603S  [H807S]
B18  R603S  [H807S]
B19  R603S  [H807S]
B20  R111S  [H807S]
B22  R603S  [H807S]
B33  R107S  [H807S]
B34  R202S  [H807S]
B35  R202S  [H807S]
B36  R113S  [H807S]
C01  W023S  [H807S]
C04  R602S  [H807S]
C38  R602S  [H807S]
C39  W501S  [H807S]
D01  W023S  [H807S]
E01  W023S  [H807S]
E05  W501S  [H807S]
E11  R113S  [H807S]
F01  W023S  [H807S]
F16  R001S  [H807S]

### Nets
(LAS+DEPS+EXS): B20.H2(H:O$1) B20.J2 B36.R2(S:I$2)
-(DP+EP): A36.N2(V:E) B18.T2(T:O) ; also sheet 4,6
-(EX+DC): B33.D2(D:O$1) C38.R2(U:F) ; also sheet 6
-(SP+PCP): B19.M2(M:O) B22.R2(T:PU0) ; also sheet 1,3,7
-(SP+PCP+LP): B22.T2(T:O) ; also sheet 6,9
-[A12*(EX+DC+LD)]: B34.R2(T:RESET) C38.U2(U:K) ; also sheet 6
-A12: A29.N2(T:PU0) B31.K2(M:PU0) B34.N2(T:PU0) B35.D2(J:PU0) B35.N2(T:PU0) C38.P2(U:E) C38.S2(U:H) ; also sheet 1,3,4,6
-AST: A20.V2(T:I$1) D10.T2(T:O)
-CLK: B09.D2(J:PU0) B09.K2(J:PU1)
-CONS: A01.U2 C37.S2(T:EN0) F07.E2(H:I$2)
-CP: B21.P2(S:D) C37.T2(T:O)
-DC: B35.S2 B36.E2(F:I$2) ; also sheet 6
-DEPS: A12.T2(V:D) B01.H2 B03.S2(T:EN0) B24.U2(V:I$2)
-DPA: A35.J2(K:D) B03.T2(T:O) B35.U2(T:PU1) ; also sheet 3
-EPA: A29.U2(T:PU1) A35.R2(S:D) B03.M2(M:O) ; also sheet 1
-EX: A29.S2 B36.D2(F:I$1) ; also sheet 6
-EXS: A12.U2(V:E) B01.E2 B03.L2(M:EN0) B24.T2(V:I$1)
-LAS: B01.L2 B19.S2(T:EN0) B20.E2(H:I$2)
-LD: B35.H2 C38.T2(U:J) ; also sheet 6
-LP: A36.E2(M:E) B19.T2(T:O) ; also sheet 4,6
-LPA: A35.N2(P:D) B03.F2(F:O) B35.K2(J:PU1) ; also sheet 3
-LPC: E05.R2(F:R) E05.U2
-PPC: A29.R2(T:RESET) A35.L2(M:D) B19.L2(M:EN0) B35.F2(J:RESET) B35.R2(T:RESET) ; also sheet 4,6
-RUN: A35.K2(K:E) A35.P2(P:E) A35.S2(S:E) B21.S2(S:F) B34.S2 B36.P2(S:I$1) ; also sheet 4
-SAC: D01.L2 ; also sheet 3
-SAC00: E01.H2
-SAC01: E01.E2
-SAC02: D01.U2
-SAC03: D01.P2
-SAC04: D01.J2
-SAC05: D01.E2
-SAC06: C01.U2
-SAC07: C01.S2
-SAC08: C01.N2
-SAC09: C01.J2
-SAC10: C01.E2
-SAC11: B01.U2
-SIK: A01.F2 B33.M2(L:I$1)
-SP: B19.P2(M:I$1) ; also sheet 1,6
-SSK: A01.L2 B34.P2(T:EN0) B36.K2(K:O$1) B36.N2(N:O$1)
-STOS: A01.R2 A40.H2(F:I$1)
-STS: A20.S2(T:EN0) B01.R2 F16.J2(K:D)
-TP: A20.R2(T:PU0) B18.R2(T:PU0) B19.R2(T:PU0) C37.R2(T:PU0) C39.E2 C39.F2(F:F)
DC: B35.T2 ; also sheet 1
EX: A29.T2
EX+DC: B33.E2(D:I$1) B36.F2(F:O$1) ; also sheet 5,7,9
GND [Supply]: A20.U2(T:G) A29.P2(T:EN0) A29.V2(T:EN1) A36.F2(M:F) A36.P2(V:F) B03.E2(F:EN0) B03.H2(F:G) B03.N2(M:G) B03.U2(T:G) B09.E2(J:EN0) B09.L2(J:EN1) B18.U2(T:G) B19.N2(M:G) B19.U2(T:G) B22.S2(T:EN0) B22.U2(T:G) B31.N2(M:G) B34.V2(T:EN1) B35.E2(J:EN0) B35.L2(J:EN1) B35.P2(T:EN0) B35.V2(T:EN1) C04.C2(K:GND) C37.U2(T:G) C38.N2(U:C) D10.S2(T:EN0) D10.U2(T:G) F01.J2 ; also sheet 1,2,3,4,5,6,7,9
LD: B35.J2 ; also sheet 7
MB10: A34.K2(N:I$1) ; also sheet 1,9
N$176: A01.J2
N$177: A34.M2(N:I$3) A35.H2(H:E)
N$178: A34.N2(N:O$1) A34.P2 B31.L2(M:EN0)
N$179: B14.M2(N:E) B31.M2(M:O)
N$180: B24.V2(V:O$1) B33.S2(R:I$1)
N$181: B34.U2(T:PU1) E11.S2(S:O$1)
N$182: B18.S2(T:EN0) B33.R2(R:O$1)
N$183: A36.S2(V:J) A36.T2(V:K)
N$184: A36.J2(M:J) A36.K2(M:K)
N$185: E05.M2(F:M) E05.N2(K:N)
N$186: E05.K2(K:K) E05.L2(F:L)
N$187: B09.J2 B19.K2(M:PU0)
N$188: D10.R2(T:PU0) E05.E2 E05.F2(F:F)
N$189: A36.M2(M:M) B03.D2(F:PU0)
N$190: A36.V2(V:M) B03.K2(M:PU0) B03.R2(T:PU0)
N$191: A12.V2(V:F) B20.F2(H:I$3)
N$192: C39.M2(F:M) C39.N2(K:N)
N$193: C39.K2(K:K) C39.L2(F:L)
N$194: C39.P2(F:P) C39.T2(T:T)
N$195: C39.R2(F:R) C39.U2 F07.H2(H:O$1) F07.J2
N$196: B36.S2(S:O$1) F07.D2(H:I$1)
N$197: F07.F2(H:I$3) F16.K2(K:E)
N$198: A02.D2 A05.F2(F:O$1)
N$199: C04.K2(K:K) E11.R2(S:I$2)
N$200: B33.L2(L:O$1) B36.L2(N:I$1)
N$201: A40.F2(F:O$1) B36.H2(K:I$1)
N$202: C04.D2(K:D) C04.M2(K:M)
N$203: A20.T2(T:O) C04.H2(K:H)
OP2: A35.F2(H:D) ; also sheet 3,6,7,9
RUN: A05.E2(F:I$1) A35.M2(M:E) B14.N2(N:F) B34.T2
SDF0: F01.E2
SDF1: F01.H2
SDF2: F01.L2
SIF0: E01.L2
SIF1: E01.R2
SIF2: E01.U2
WTE: A34.L2(N:I$2) ; also sheet 1,3,6
WTF: B36.J2(K:I$2) B36.M2(N:I$2) ; also sheet 1,3,5,6
WTS: C04.J2(K:J) ; also sheet 6
Unconnected: A01.A2 A01.B2 A01.C2 A01.D2 A01.E2 A01.H2 A01.K2 A01.M2 A01.N2 A01.P2 A01.S2 A01.T2 A01.V2 A20.P2(M:I$1) A34.F2(H:I$3) A36.H2(M:H) A36.L2(M:L) A36.R2(V:H) A36.U2(V:L) A40.D2(D:O$1) A40.E2(D:I$1) A40.J2(J:O$1) A40.K2(J:I$1) A40.L2(L:O$1) A40.M2(L:I$1) A40.N2(N:O$1) A40.P2(N:I$1) A40.R2(R:O$1) A40.S2(R:I$1) A40.T2(T:O$1) A40.U2(T:I$1) A40.V2(T:I$2) B01.A2 B01.B2 B01.C2 B01.D2 B01.F2 B01.J2 B01.K2 B01.M2 B01.N2 B01.P2 B01.S2 B01.T2 B01.V2 B03.J2(F:I$1) B03.P2(M:I$1) B03.V2(T:I$1) B09.F2(J:RESET) B09.H2 B09.M2(J:SET) B14.L2(N:D) B18.D2(F:PU0) B18.E2(F:EN0) B18.F2(F:O) B18.H2(F:G) B18.J2(F:I$1) B18.K2(M:PU0) B18.L2(M:EN0) B18.M2(M:O) B18.N2(M:G) B18.P2(M:I$1) B18.V2(T:I$1) B19.D2(F:PU0) B19.E2(F:EN0) B19.F2(F:O) B19.H2(F:G) B19.J2(F:I$1) B19.V2(T:I$1) B20.D2(H:I$1) B21.R2(S:E) B22.D2(F:PU0) B22.E2(F:EN0) B22.F2(F:O) B22.H2(F:G) B22.J2(F:I$1) B22.V2(T:I$1) B31.P2(M:I$1) B33.F2(F:O$1) B33.H2(F:I$1) B33.J2(J:O$1) B33.K2(J:I$1) B33.N2(N:O$1) B33.P2(N:I$1) B33.T2(T:O$1) B33.U2(T:I$1) B33.V2(T:I$2) B34.D2(J:PU0) B34.E2(J:EN0) B34.F2(J:RESET) B34.H2 B34.J2 B34.K2(J:PU1) B34.L2(J:EN1) B34.M2(J:SET) B35.M2(J:SET) B36.T2(V:I$1) B36.U2(V:I$2) B36.V2(V:O$1) C01.A2 C01.B2 C01.C2 C01.D2 C01.F2 C01.H2 C01.K2 C01.L2 C01.M2 C01.P2 C01.R2 C01.T2 C01.V2 C04.E2(K:E) C04.F2(K:F) C04.L2(K:L) C04.N2(U:C) C04.P2(U:E) C04.R2(U:F) C04.S2(U:H) C04.T2(U:J) C04.U2(U:K) C04.V2(U:L) C37.V2(T:I$1) C38.D2(K:D) C38.E2(K:E) C38.F2(K:F) C38.H2(K:H) C38.J2(K:J) C38.K2(K:K) C38.L2(K:L) C38.M2(K:M) C38.V2(U:L) C39.D2 C39.S2(T:S) D01.A2 D01.B2 D01.C2 D01.D2 D01.F2 D01.H2 D01.K2 D01.M2 D01.N2 D01.R2 D01.S2 D01.T2 D01.V2 D10.J2(F:I$1) D10.P2(M:I$1) D10.V2(T:I$1) E01.A2 E01.B2 E01.C2 E01.D2 E01.F2 E01.J2 E01.K2 E01.M2 E01.N2 E01.P2 E01.S2 E01.T2 E01.V2 E05.D2 E05.P2(F:P) E05.S2(T:S) E05.T2(T:T) E11.P2(S:I$1) F01.A2 F01.B2 F01.C2 F01.D2 F01.F2 F01.K2 F01.M2 F01.N2 F01.P2 F01.R2 F01.S2 F01.T2 F01.U2 F01.V2 F07.T2(U:I$3)

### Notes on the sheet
- Switch Register
- * | *
- *
- *
- * NOTE: This module is not in the
- standard machine.  For Auto Restart
- feature only.  Disable Auto Restart
- by removing the module.
- Control
- D-BS-8S-0-15

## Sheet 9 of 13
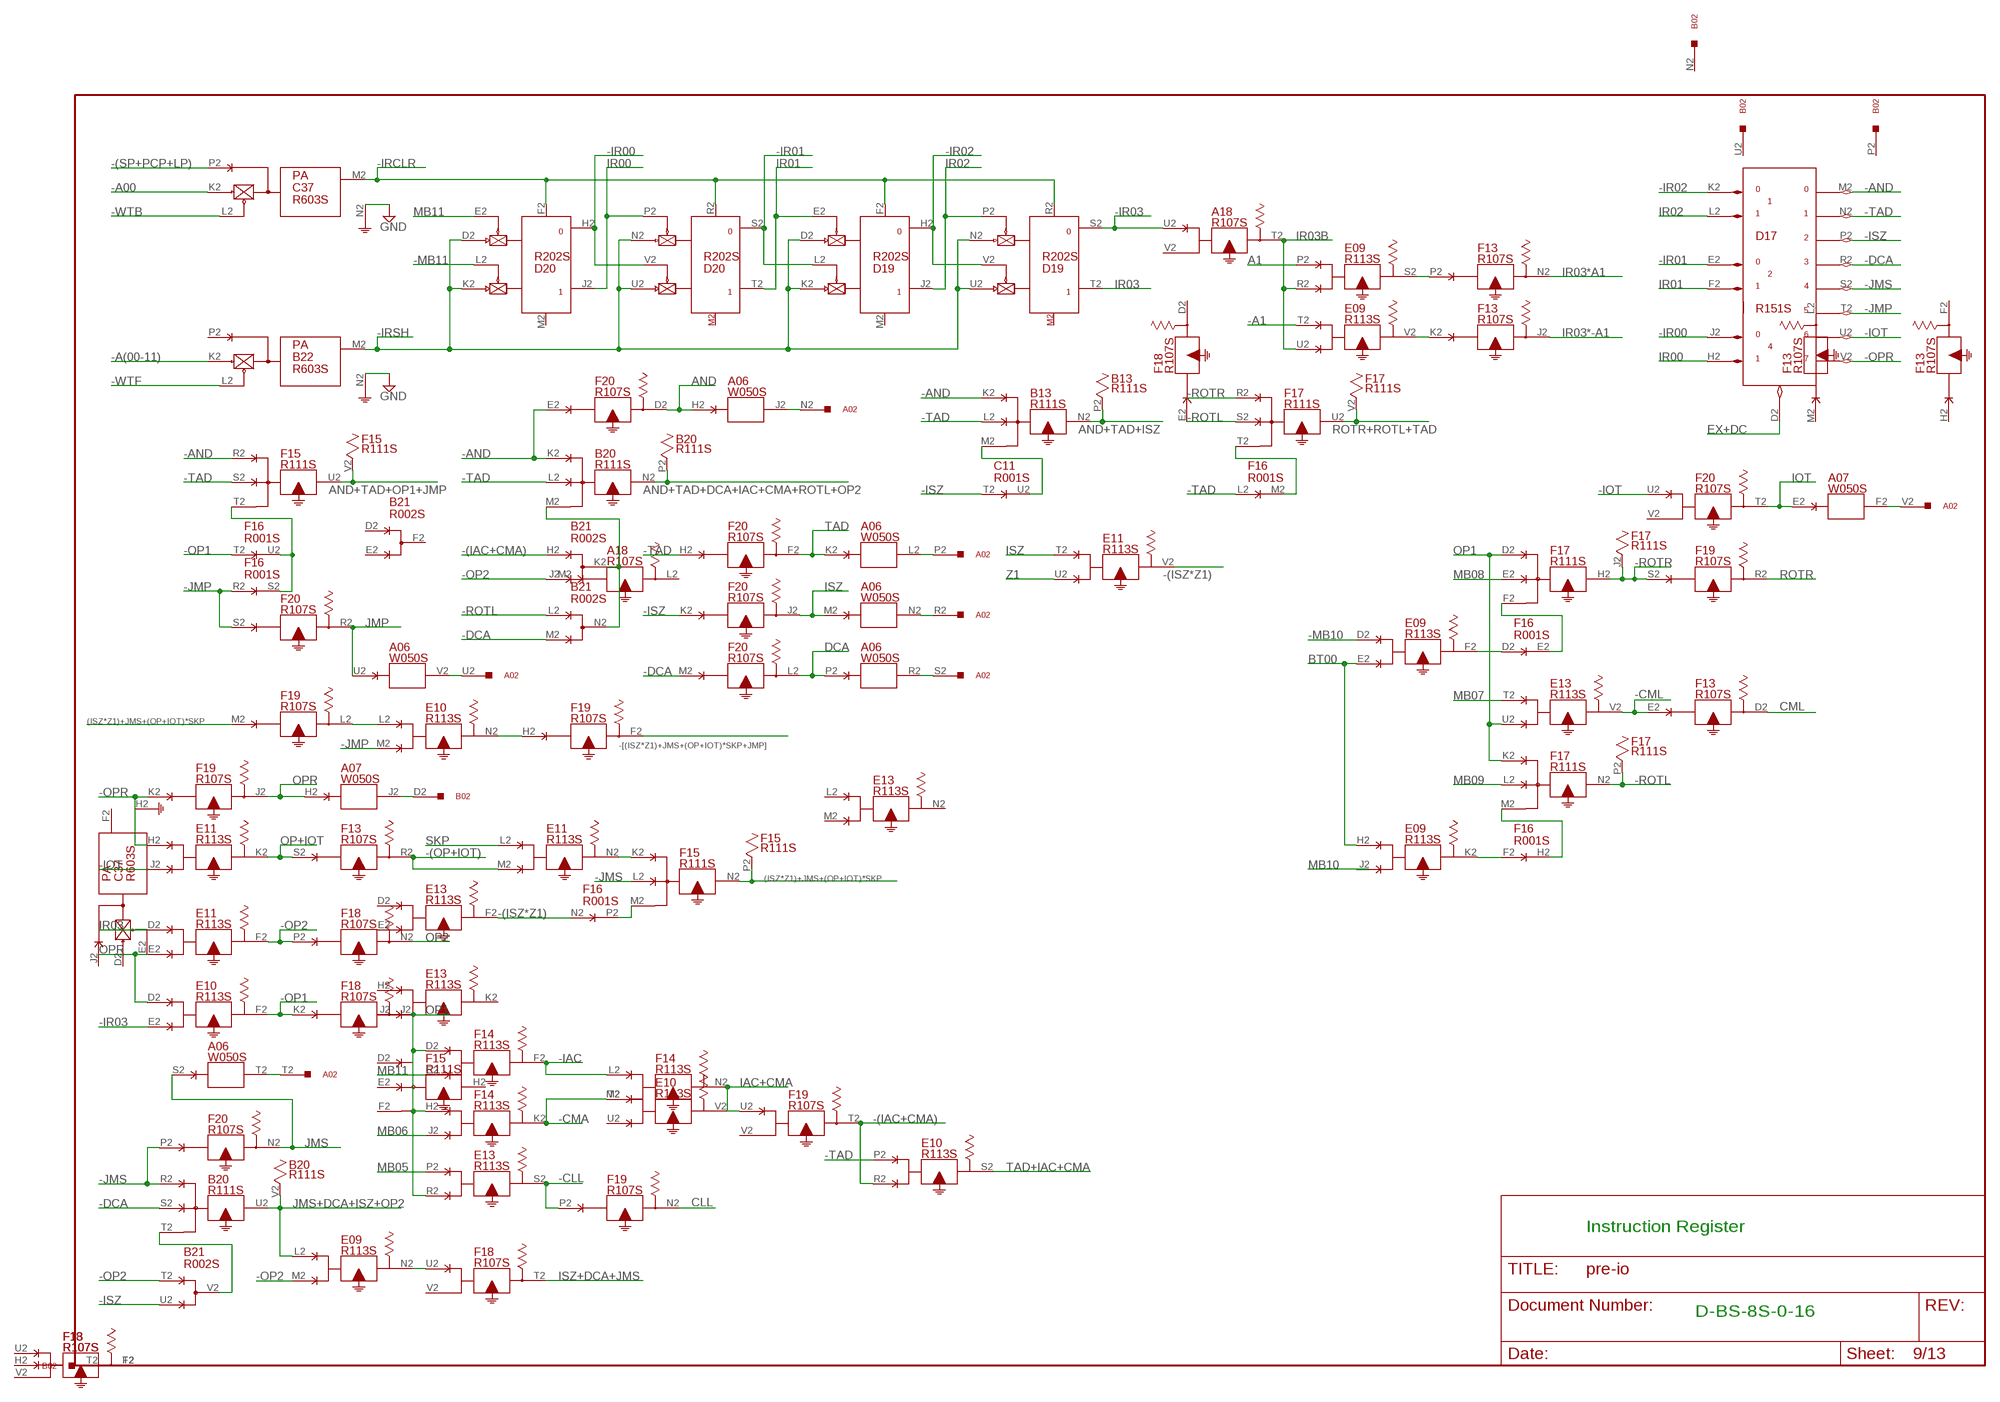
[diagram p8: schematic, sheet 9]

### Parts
A07  W050S  [H807S]
D17  R151S  [H807S]
D19  R202S  [H807S]
D20  R202S  [H807S]
E09  R113S  [H807S]
F14  R113S  [H807S]
F17  R111S  [H807S]
F19  R107S  [H807S]
F20  R107S  [H807S]

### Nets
(ISZ*Z1)+JMS+(OP+IOT)*SKP: F15.N2(N:O$1) F15.P2 F19.M2(L:I$1)
-(IAC+CMA): B21.H2(K:D) E10.R2(S:I$2) F19.T2(T:O$1)
-(ISZ*Z1): E11.V2(V:O$1) F16.N2(P:D)
-(OP+IOT): E11.M2(N:I$2) F13.R2(R:O$1) ; also sheet 1,6
-(SP+PCP+LP): C37.P2(M:I$1) ; also sheet 6,8
-[(ISZ*Z1)+JMS+(OP+IOT)*SKP+JMP]: F19.F2(F:O$1)
-A00: C37.K2(M:PU0) ; also sheet 3,4,5
-A1: E09.T2(V:I$1) ; also sheet 6
-A(00-11): B22.K2(M:PU0) ; also sheet 1,3,4,5,7
-AND: B13.K2(N:I$1) B20.K2(N:I$1) D17.M2(M) F15.R2(U:I$1) F20.E2(D:I$1)
-CLL: E13.S2(S:O$1) F19.P2(N:I$1) ; also sheet 3
-CMA: F14.K2(K:O$1) F14.M2(N:I$2)
-CML: E13.V2(V:O$1) F13.E2(D:I$1) ; also sheet 3
-DCA: B20.S2(U:I$2) B21.M2(N:E) D17.R2(R) F20.M2(L:I$1)
-IAC: F14.F2(F:O$1) F14.L2(N:I$1)
-IOT: D17.U2(U) E11.J2(K:I$2) F20.U2(T:I$1)
-IR00: D17.J2(J) D20.H2 D20.V2(T:EN1)
-IR01: D17.E2(E) D19.L2(J:EN1) D20.S2
-IR02: D17.K2(K) D19.H2 D19.V2(T:EN1)
-IR03: A18.U2(T:I$1) D19.S2 E10.E2(F:I$2) ; also sheet 6
-IRCLR: C37.M2(M:O) D19.F2(J:RESET) D19.R2(T:RESET) D20.F2(J:RESET) D20.R2(T:RESET)
-IRSH: B22.M2(M:O) D19.D2(J:PU0) D19.K2(J:PU1) D19.N2(T:PU0) D19.U2(T:PU1) D20.D2(J:PU0) D20.K2(J:PU1) D20.N2(T:PU0) D20.U2(T:PU1)
-ISZ: B21.U2(V:E) C11.T2(U:D) D17.P2(P) F20.K2(J:I$1)
-JMP: D17.T2(T) E10.M2(N:I$2) F16.R2(S:D) F20.S2(R:I$1)
-JMS: B20.R2(U:I$1) D17.S2(S) F15.L2(N:I$2) F20.P2(N:I$1)
-MB10: E09.D2(F:I$1) ; also sheet 1,2
-MB11: D20.L2(J:EN1) ; also sheet 1,2
-OP1: E10.F2(F:O$1) F16.T2(U:D) F18.K2(J:I$1)
-OP2: B21.J2(K:E) B21.T2(V:D) E09.M2(N:I$2) E11.F2(F:O$1) F18.P2(N:I$1)
-OPR: D17.V2(V) E11.H2(K:I$1) F19.K2(J:I$1) ; also sheet 1
-ROTL: B21.L2(N:D) F17.N2(N:O$1) F17.P2 F17.S2(U:I$2)
-ROTR: F17.H2(H:O$1) F17.J2 F17.R2(U:I$1) F19.S2(R:I$1) ; also sheet 3
-TAD: B13.L2(N:I$2) B20.L2(N:I$2) D17.N2(N) E10.P2(S:I$1) F15.S2(U:I$2) F16.L2(M:D) F20.H2(F:I$1)
-WTB: C37.L2(M:EN0) ; also sheet 6
-WTF: B22.L2(M:EN0) ; also sheet 6,7
A1: E09.P2(S:I$1) ; also sheet 6
AND: A06.H2(J:I$1) F20.D2(D:O$1)
AND+TAD+DCA+IAC+CMA+ROTL+OP2: B20.N2(N:O$1) B20.P2
AND+TAD+ISZ: B13.N2(N:O$1) B13.P2 ; also sheet 1
AND+TAD+OP1+JMP: F15.U2(U:O$1) F15.V2 ; also sheet 6
BT00: E09.E2(F:I$2) E09.H2(K:I$1) ; also sheet 4,7
CLL: F19.N2(N:O$1) ; also sheet 3
CML: F13.D2(D:O$1) ; also sheet 3
DCA: A06.P2(R:I$1) F20.L2(L:O$1) ; also sheet 6
EX+DC: D17.D2(D) ; also sheet 5,7,8
GND [Supply]: B22.N2(M:G) C37.N2(M:G) ; also sheet 1,2,3,4,5,6,7,8
IAC+CMA: F14.N2(N:O$1) F19.U2(T:I$1) ; also sheet 7
IOT: A07.E2(F:I$1) F20.T2(T:O$1)
IR00: D17.H2(H) D20.J2 D20.P2(T:EN0)
IR01: D17.F2(F) D19.E2(J:EN0) D20.T2
IR02: D17.L2(L) D19.J2 D19.P2(T:EN0)
IR03: D19.T2 E11.D2(F:I$1) ; also sheet 6
IR03*-A1: F13.J2(J:O$1) ; also sheet 6
IR03*A1: F13.N2(N:O$1) ; also sheet 6
IR03B: A18.T2(T:O$1) E09.R2(S:I$2) E09.U2(V:I$2)
ISZ: A06.M2(N:I$1) E11.T2(V:I$1) F20.J2(J:O$1)
ISZ+DCA+JMS: F18.T2(T:O$1)
JMP: A06.U2(V:I$1) F20.R2(R:O$1) ; also sheet 6
JMS: A06.S2(T:I$1) F20.N2(N:O$1) ; also sheet 6
JMS+DCA+ISZ+OP2: B20.U2(U:O$1) B20.V2 E09.L2(N:I$1)
MB05: E13.P2(S:I$1) ; also sheet 1,3
MB06: F14.J2(K:I$2) ; also sheet 1,3,7
MB07: E13.T2(V:I$1) ; also sheet 1,3
MB08: F17.E2(H:I$2) ; also sheet 1,3,6
MB09: F17.L2(N:I$2) ; also sheet 1,3
MB11: D20.E2(J:EN0) F14.E2(F:I$2) ; also sheet 1,6,7
N$204: A02.V2 A07.F2(F:O$1)
N$205: A02.N2 A06.J2(J:O$1)
N$206: F15.T2(U:I$3) F16.S2(S:E) F16.U2(U:E)
N$207: B20.M2(N:I$3) B21.K2(K:F) B21.N2(N:F)
N$208: B13.M2(N:I$3) C11.U2(U:E)
N$209: A02.P2 A06.L2(L:O$1)
N$210: E09.S2(S:O$1) F13.P2(N:I$1)
N$211: F16.M2(M:E) F17.T2(U:I$3)
N$212: E09.V2(V:O$1) F13.K2(J:I$1)
N$213: A02.R2 A06.N2(N:O$1)
N$214: F16.E2(E:E) F17.F2(H:I$3)
N$215: F16.H2(H:E) F17.M2(N:I$3)
N$216: A02.U2 A06.V2(V:O$1)
N$217: E09.F2(F:O$1) F16.D2(E:D)
N$218: E09.K2(K:O$1) F16.F2(H:D)
N$219: E10.L2(N:I$1) F19.L2(L:O$1)
N$220: A07.J2(J:O$1) B02.D2
N$221: E11.N2(N:O$1) F15.K2(N:I$1)
N$222: E10.N2(N:O$1) F19.H2(F:I$1)
N$223: B20.T2(U:I$3) B21.V2(V:F)
N$224: A02.T2 A06.T2(T:O$1)
N$225: F15.M2(N:I$3) F16.P2(P:E)
N$226: A02.S2 A06.R2(R:O$1)
N$227: E09.N2(N:O$1) F18.U2(T:I$1)
OP1: E13.R2(S:I$2) E13.U2(V:I$2) F14.D2(F:I$1) F14.H2(K:I$1) F17.D2(H:I$1) F17.K2(N:I$1) F18.J2(J:O$1) ; also sheet 6,7
OP2: F18.N2(N:O$1) ; also sheet 3,6,7,8
OP+IOT: E11.K2(K:O$1) F13.S2(R:I$1)
OPR: A07.H2(J:I$1) E10.D2(F:I$1) E11.E2(F:I$2) F19.J2(J:O$1)
ROTR: F19.R2(R:O$1) ; also sheet 6
ROTR+ROTL+TAD: F17.U2(U:O$1) F17.V2 ; also sheet 3
SKP: E11.L2(N:I$1) ; also sheet 3
TAD: A06.K2(L:I$1) F20.F2(F:O$1) ; also sheet 6
TAD+IAC+CMA: E10.S2(S:O$1) ; also sheet 3
Z1: E11.U2(V:I$2) ; also sheet 7
Unconnected: A07.K2(L:I$1) A07.L2(L:O$1) A07.M2(N:I$1) A07.N2(N:O$1) A07.P2(R:I$1) A07.R2(R:O$1) A07.S2(T:I$1) A07.T2(T:O$1) A07.U2(V:I$1) A07.V2(V:O$1) A18.V2(T:I$2) B22.P2(M:I$1) D19.M2(J:SET) D20.M2(J:SET) E09.J2(K:I$2) F13.V2(T:I$2) F14.P2(S:I$1) F14.R2(S:I$2) F14.S2(S:O$1) F14.T2(V:I$1) F14.U2(V:I$2) F14.V2(V:O$1) F15.F2(H:I$3) F18.V2(T:I$2) F19.D2(D:O$1) F19.E2(D:I$1) F19.V2(T:I$2) F20.V2(T:I$2)

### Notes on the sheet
- Instruction Register
- D-BS-8S-0-16

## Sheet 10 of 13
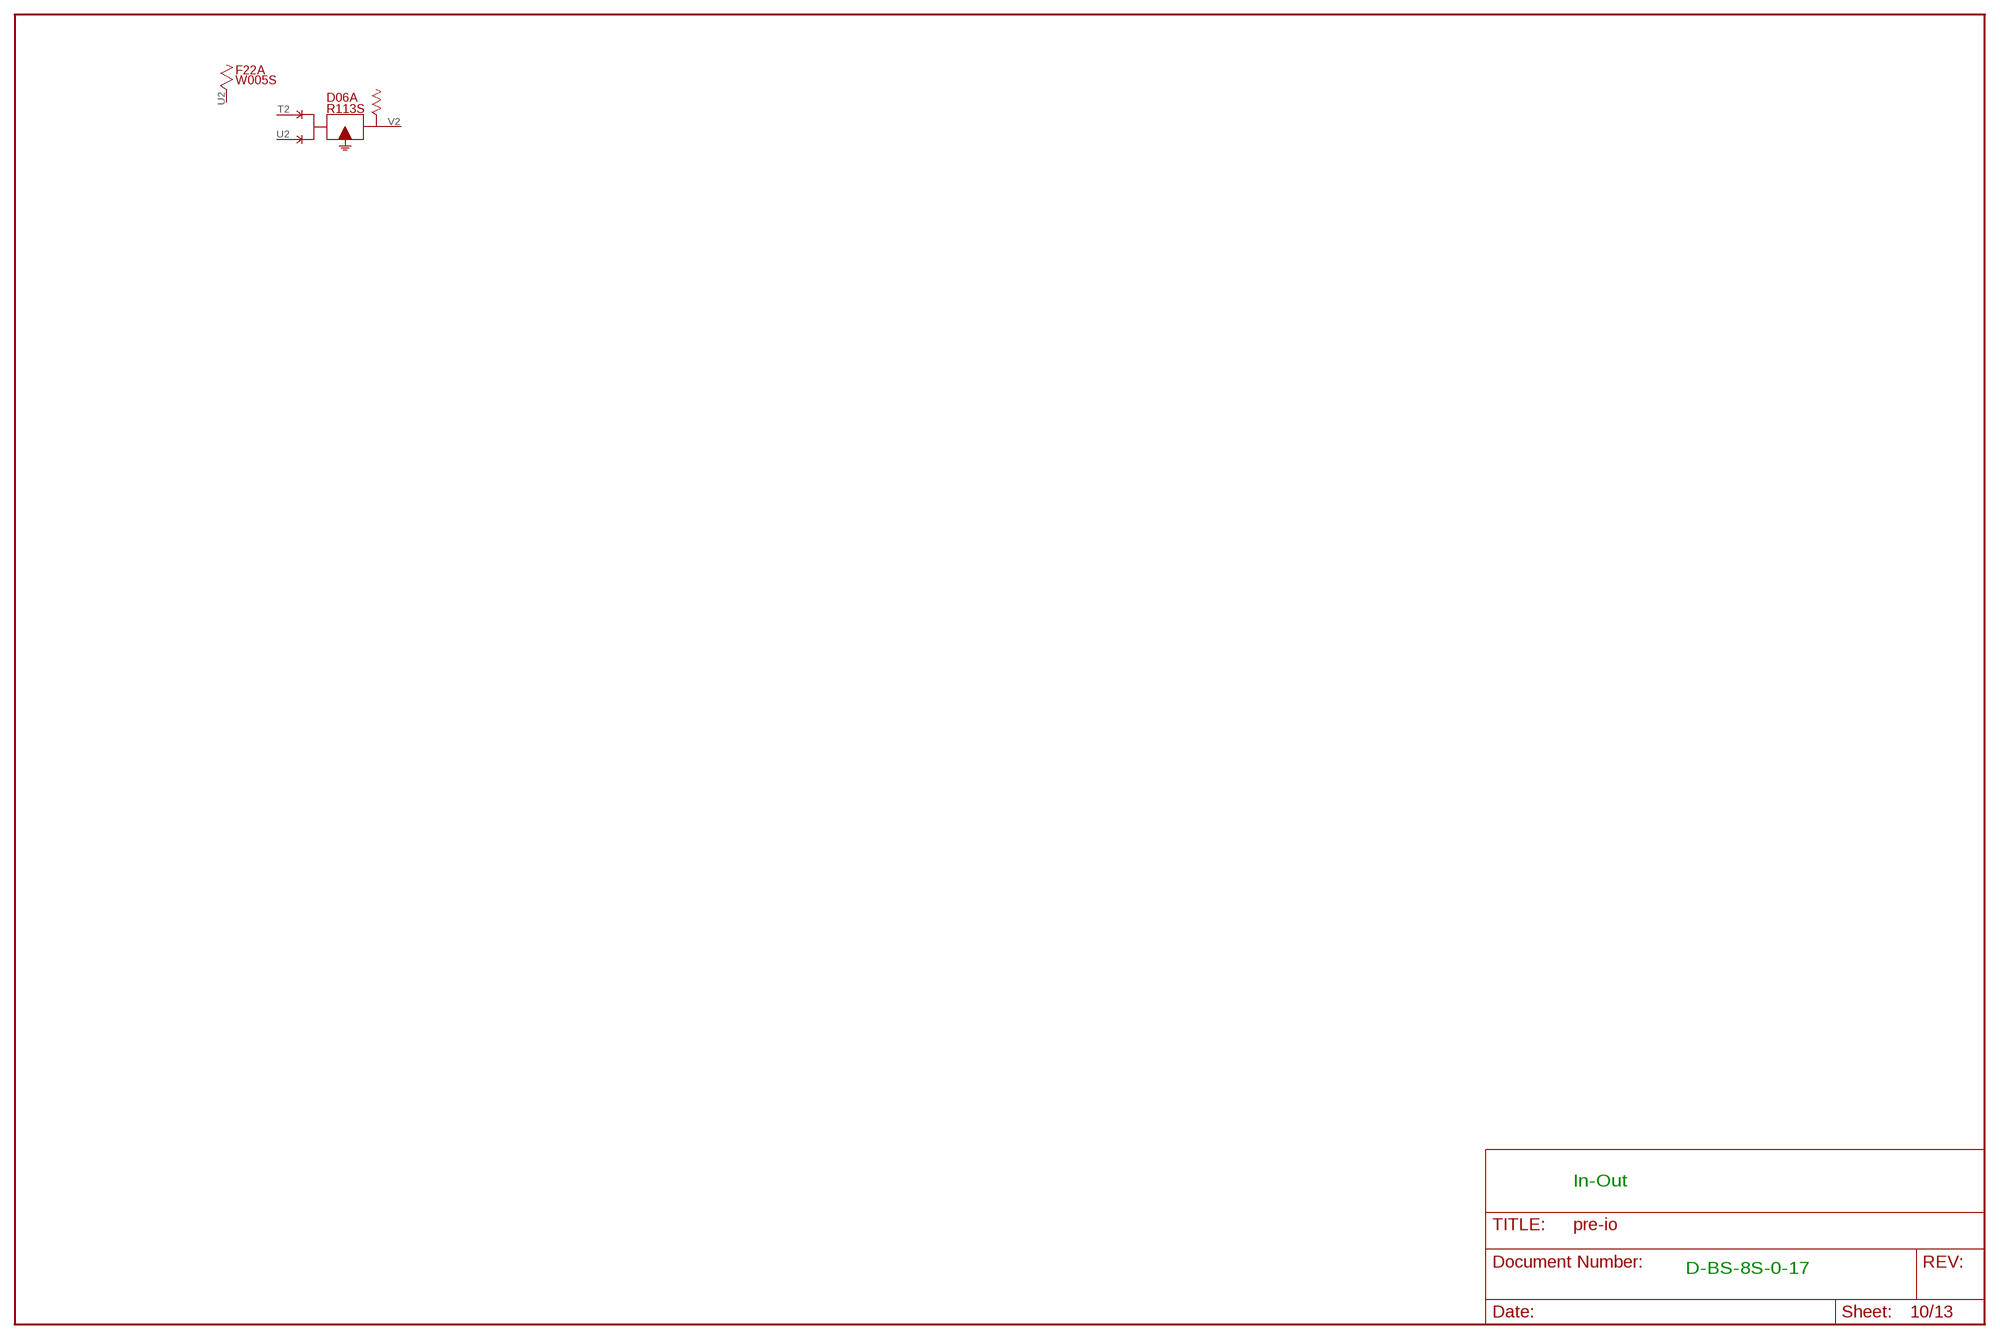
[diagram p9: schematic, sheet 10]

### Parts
D06A  R113S  [H807S]
F22A  W005S  [H807S]
Unconnected: D06A.D2(F:I$1) D06A.E2(F:I$2) D06A.F2(F:O$1) D06A.H2(K:I$1) D06A.J2(K:I$2) D06A.K2(K:O$1) D06A.L2(N:I$1) D06A.M2(N:I$2) D06A.N2(N:O$1) D06A.P2(S:I$1) D06A.R2(S:I$2) D06A.S2(S:O$1) D06A.T2(V:I$1) D06A.U2(V:I$2) D06A.V2(V:O$1) F22A.D2 F22A.E2 F22A.F2 F22A.H2 F22A.J2 F22A.K2 F22A.L2 F22A.M2 F22A.N2 F22A.P2 F22A.R2 F22A.S2 F22A.T2 F22A.U2 F22A.V2

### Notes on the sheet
- In-Out
- D-BS-8S-0-17

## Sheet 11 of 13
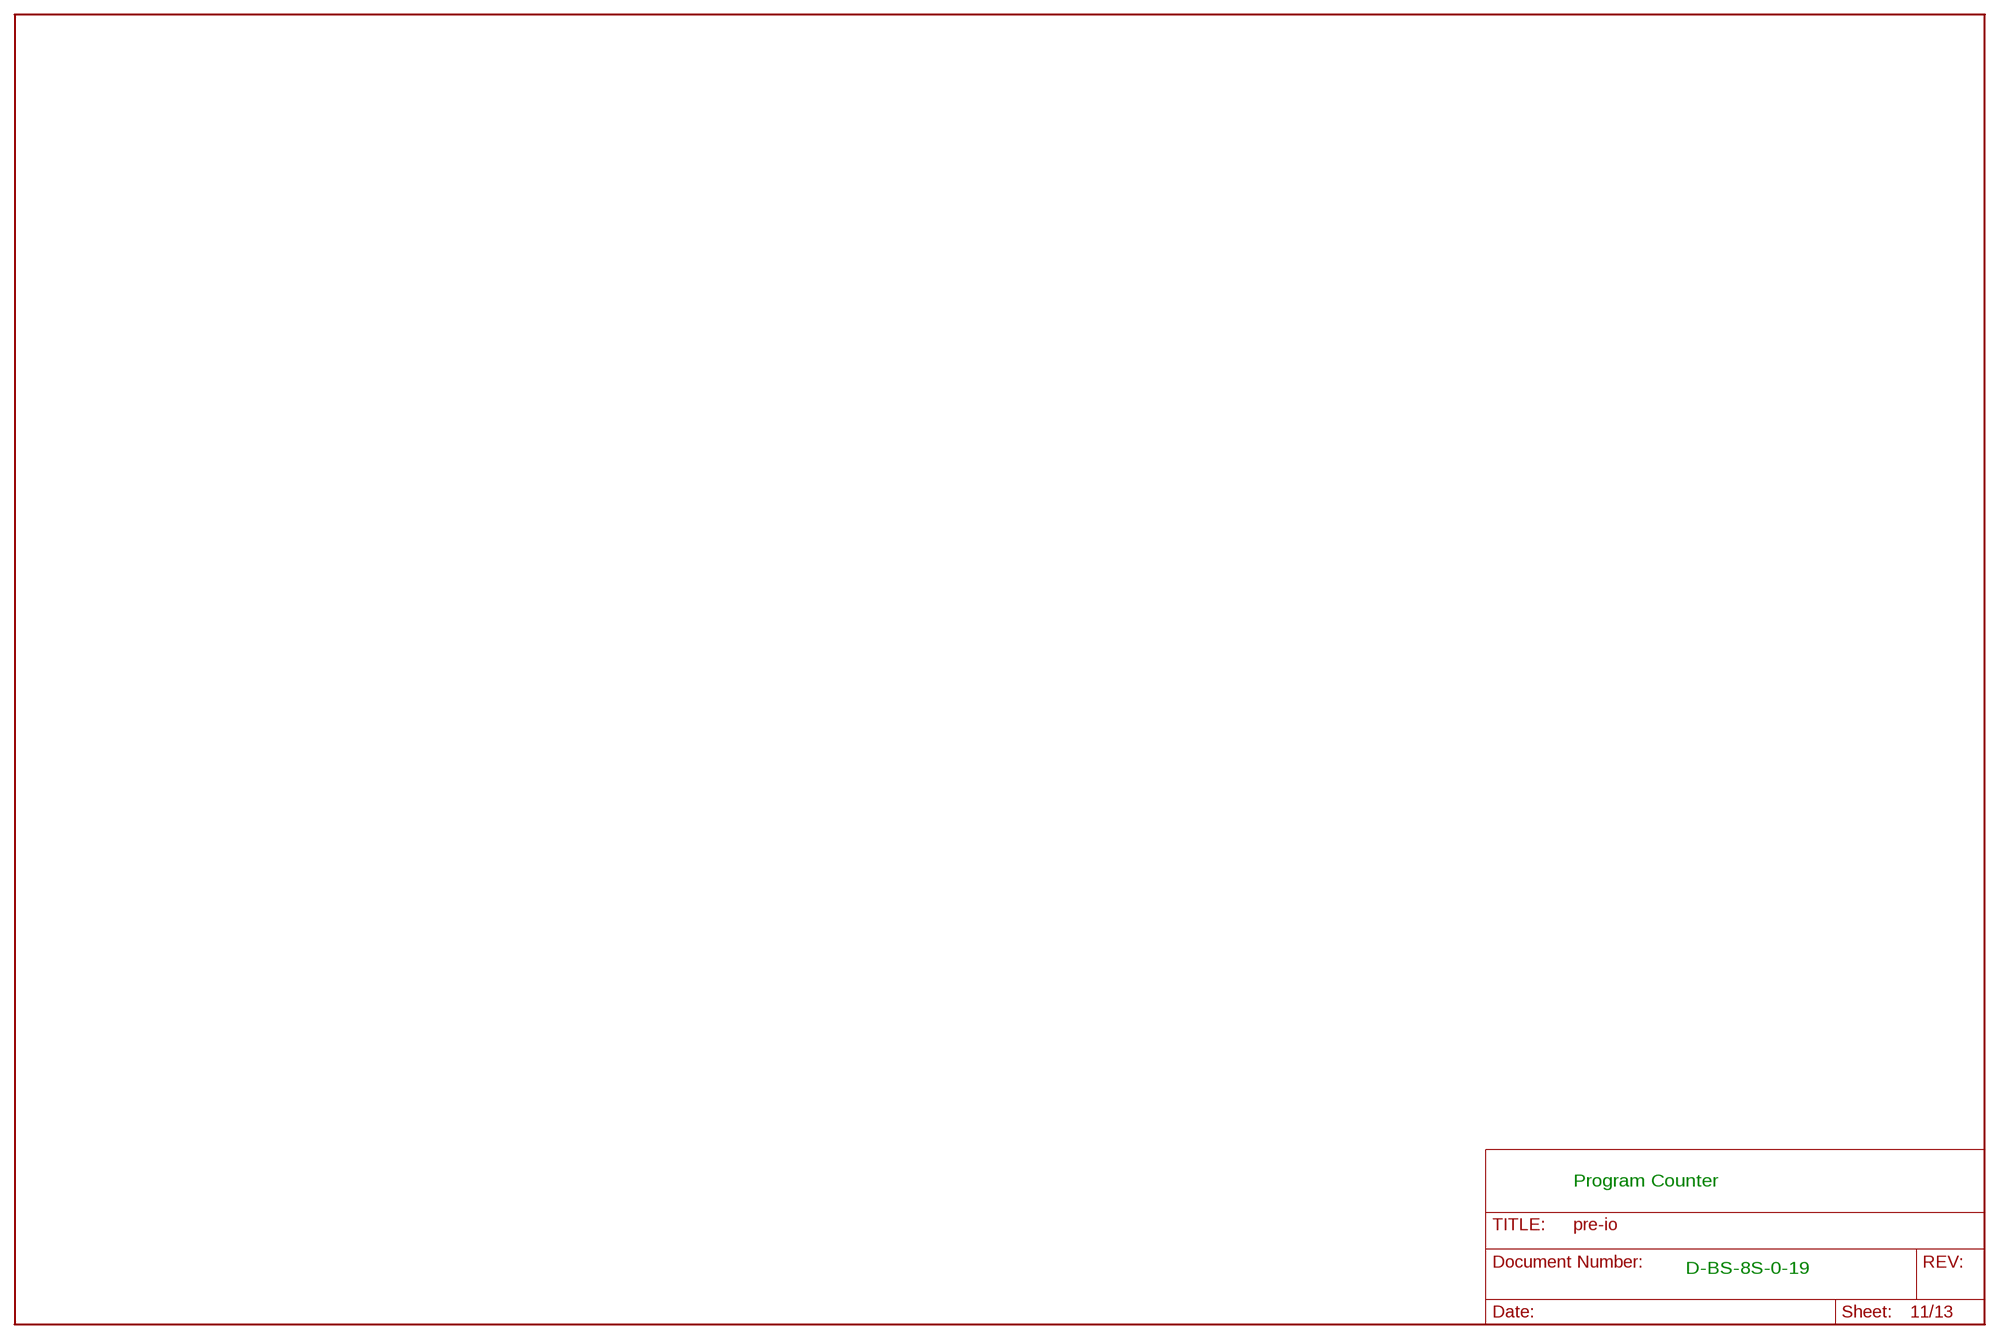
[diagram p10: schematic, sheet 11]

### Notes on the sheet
- Program Counter
- D-BS-8S-0-19

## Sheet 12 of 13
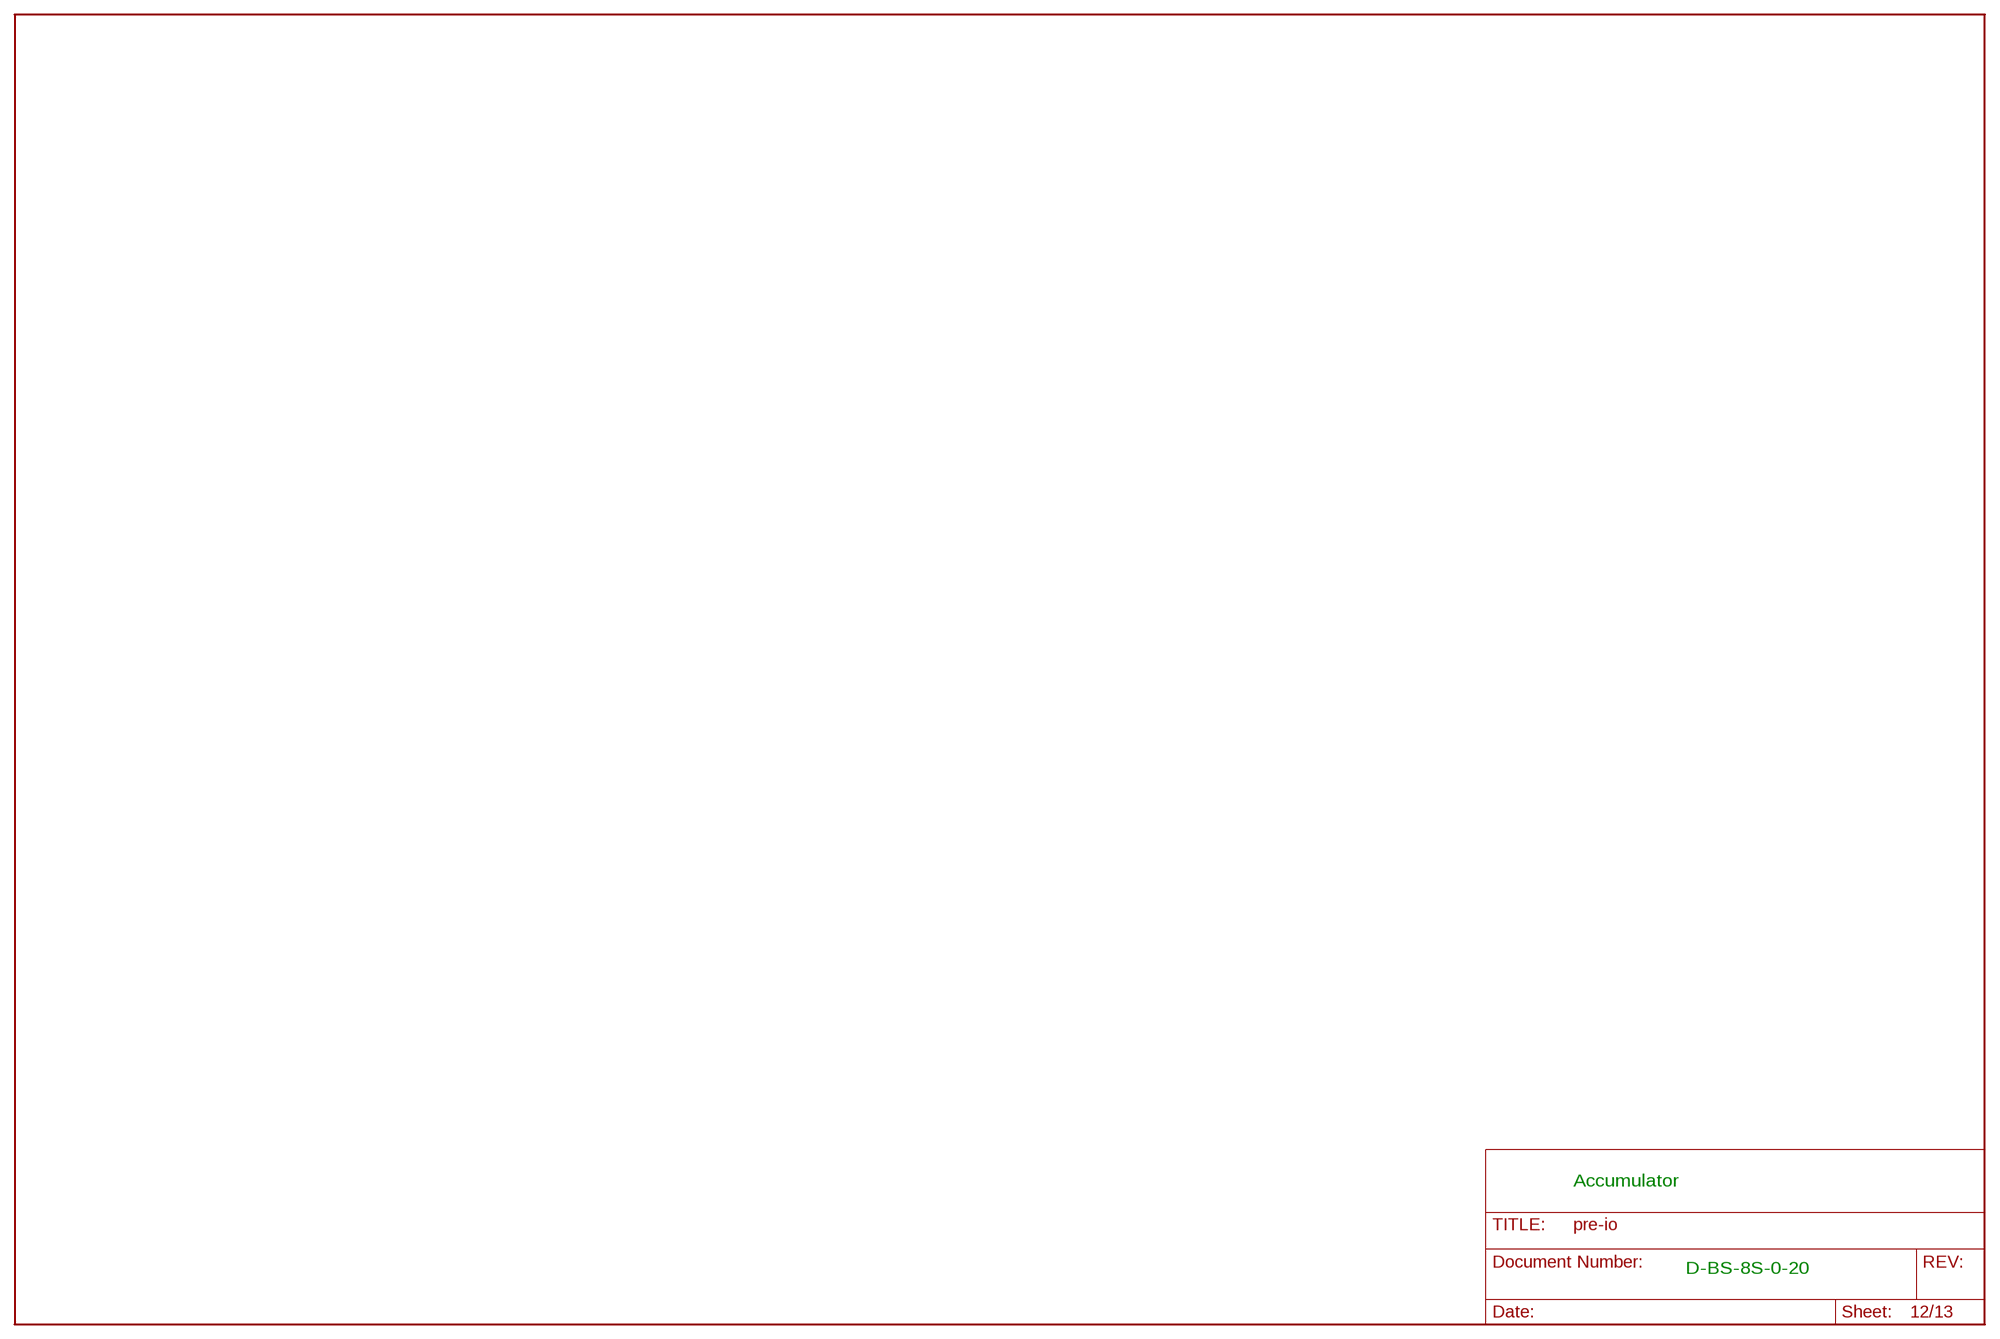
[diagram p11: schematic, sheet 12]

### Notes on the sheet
- Accumulator
- D-BS-8S-0-20

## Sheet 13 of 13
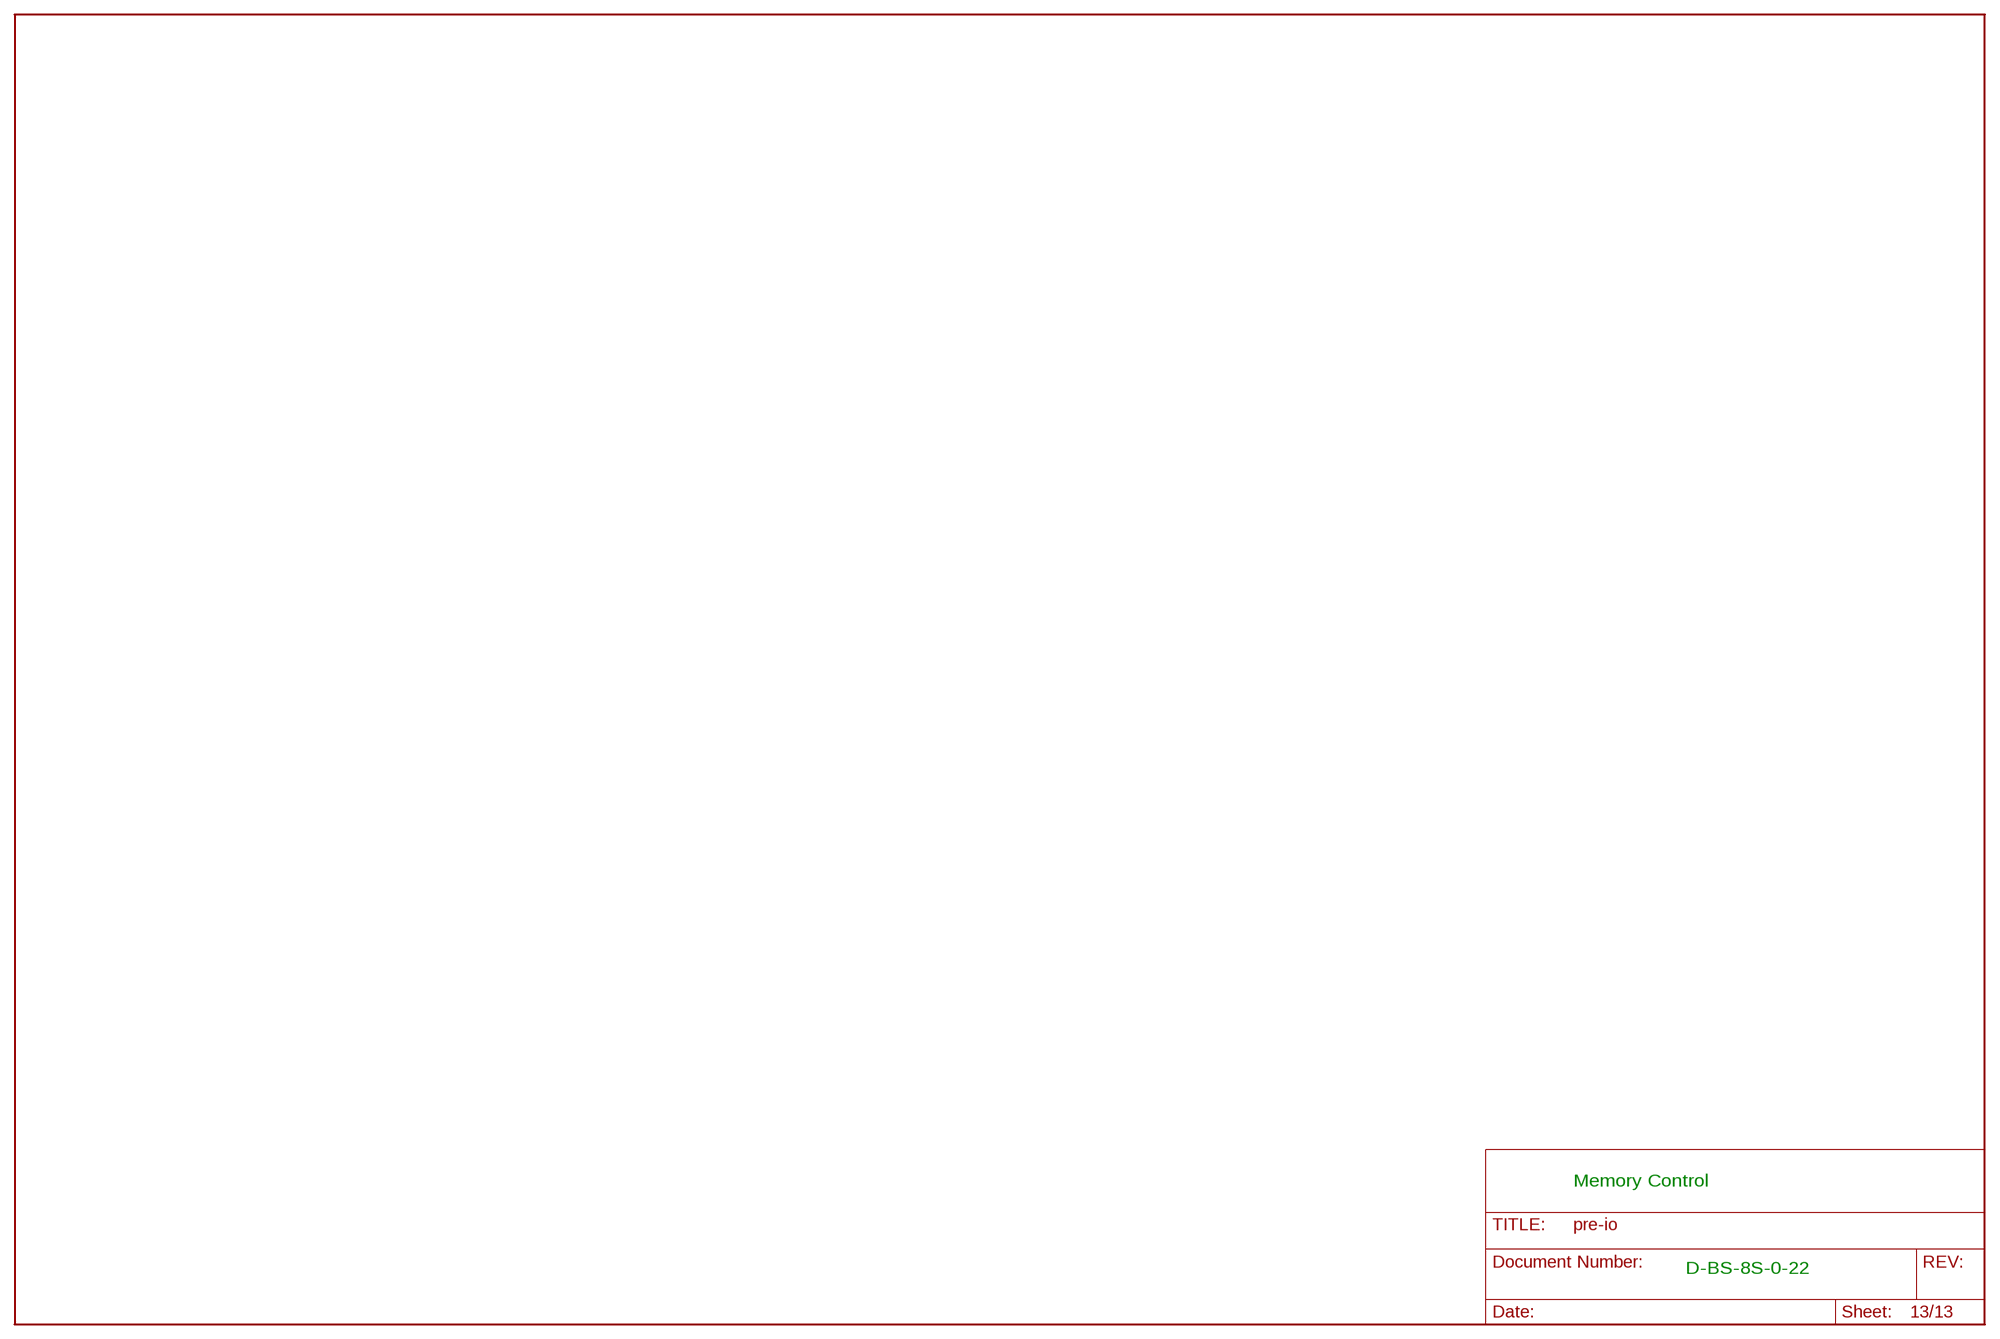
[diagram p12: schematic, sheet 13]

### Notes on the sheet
- Memory Control
- D-BS-8S-0-22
